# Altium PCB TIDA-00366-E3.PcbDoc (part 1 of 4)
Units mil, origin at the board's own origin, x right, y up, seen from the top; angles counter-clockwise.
Board outline 6298.95 x 6141.73 mil, 4 copper layers (Top Layer, GND, PWR, Bottom Layer), stack 79.834 mil thick; 362 components, 168 nets, 919 pads, 271 vias.
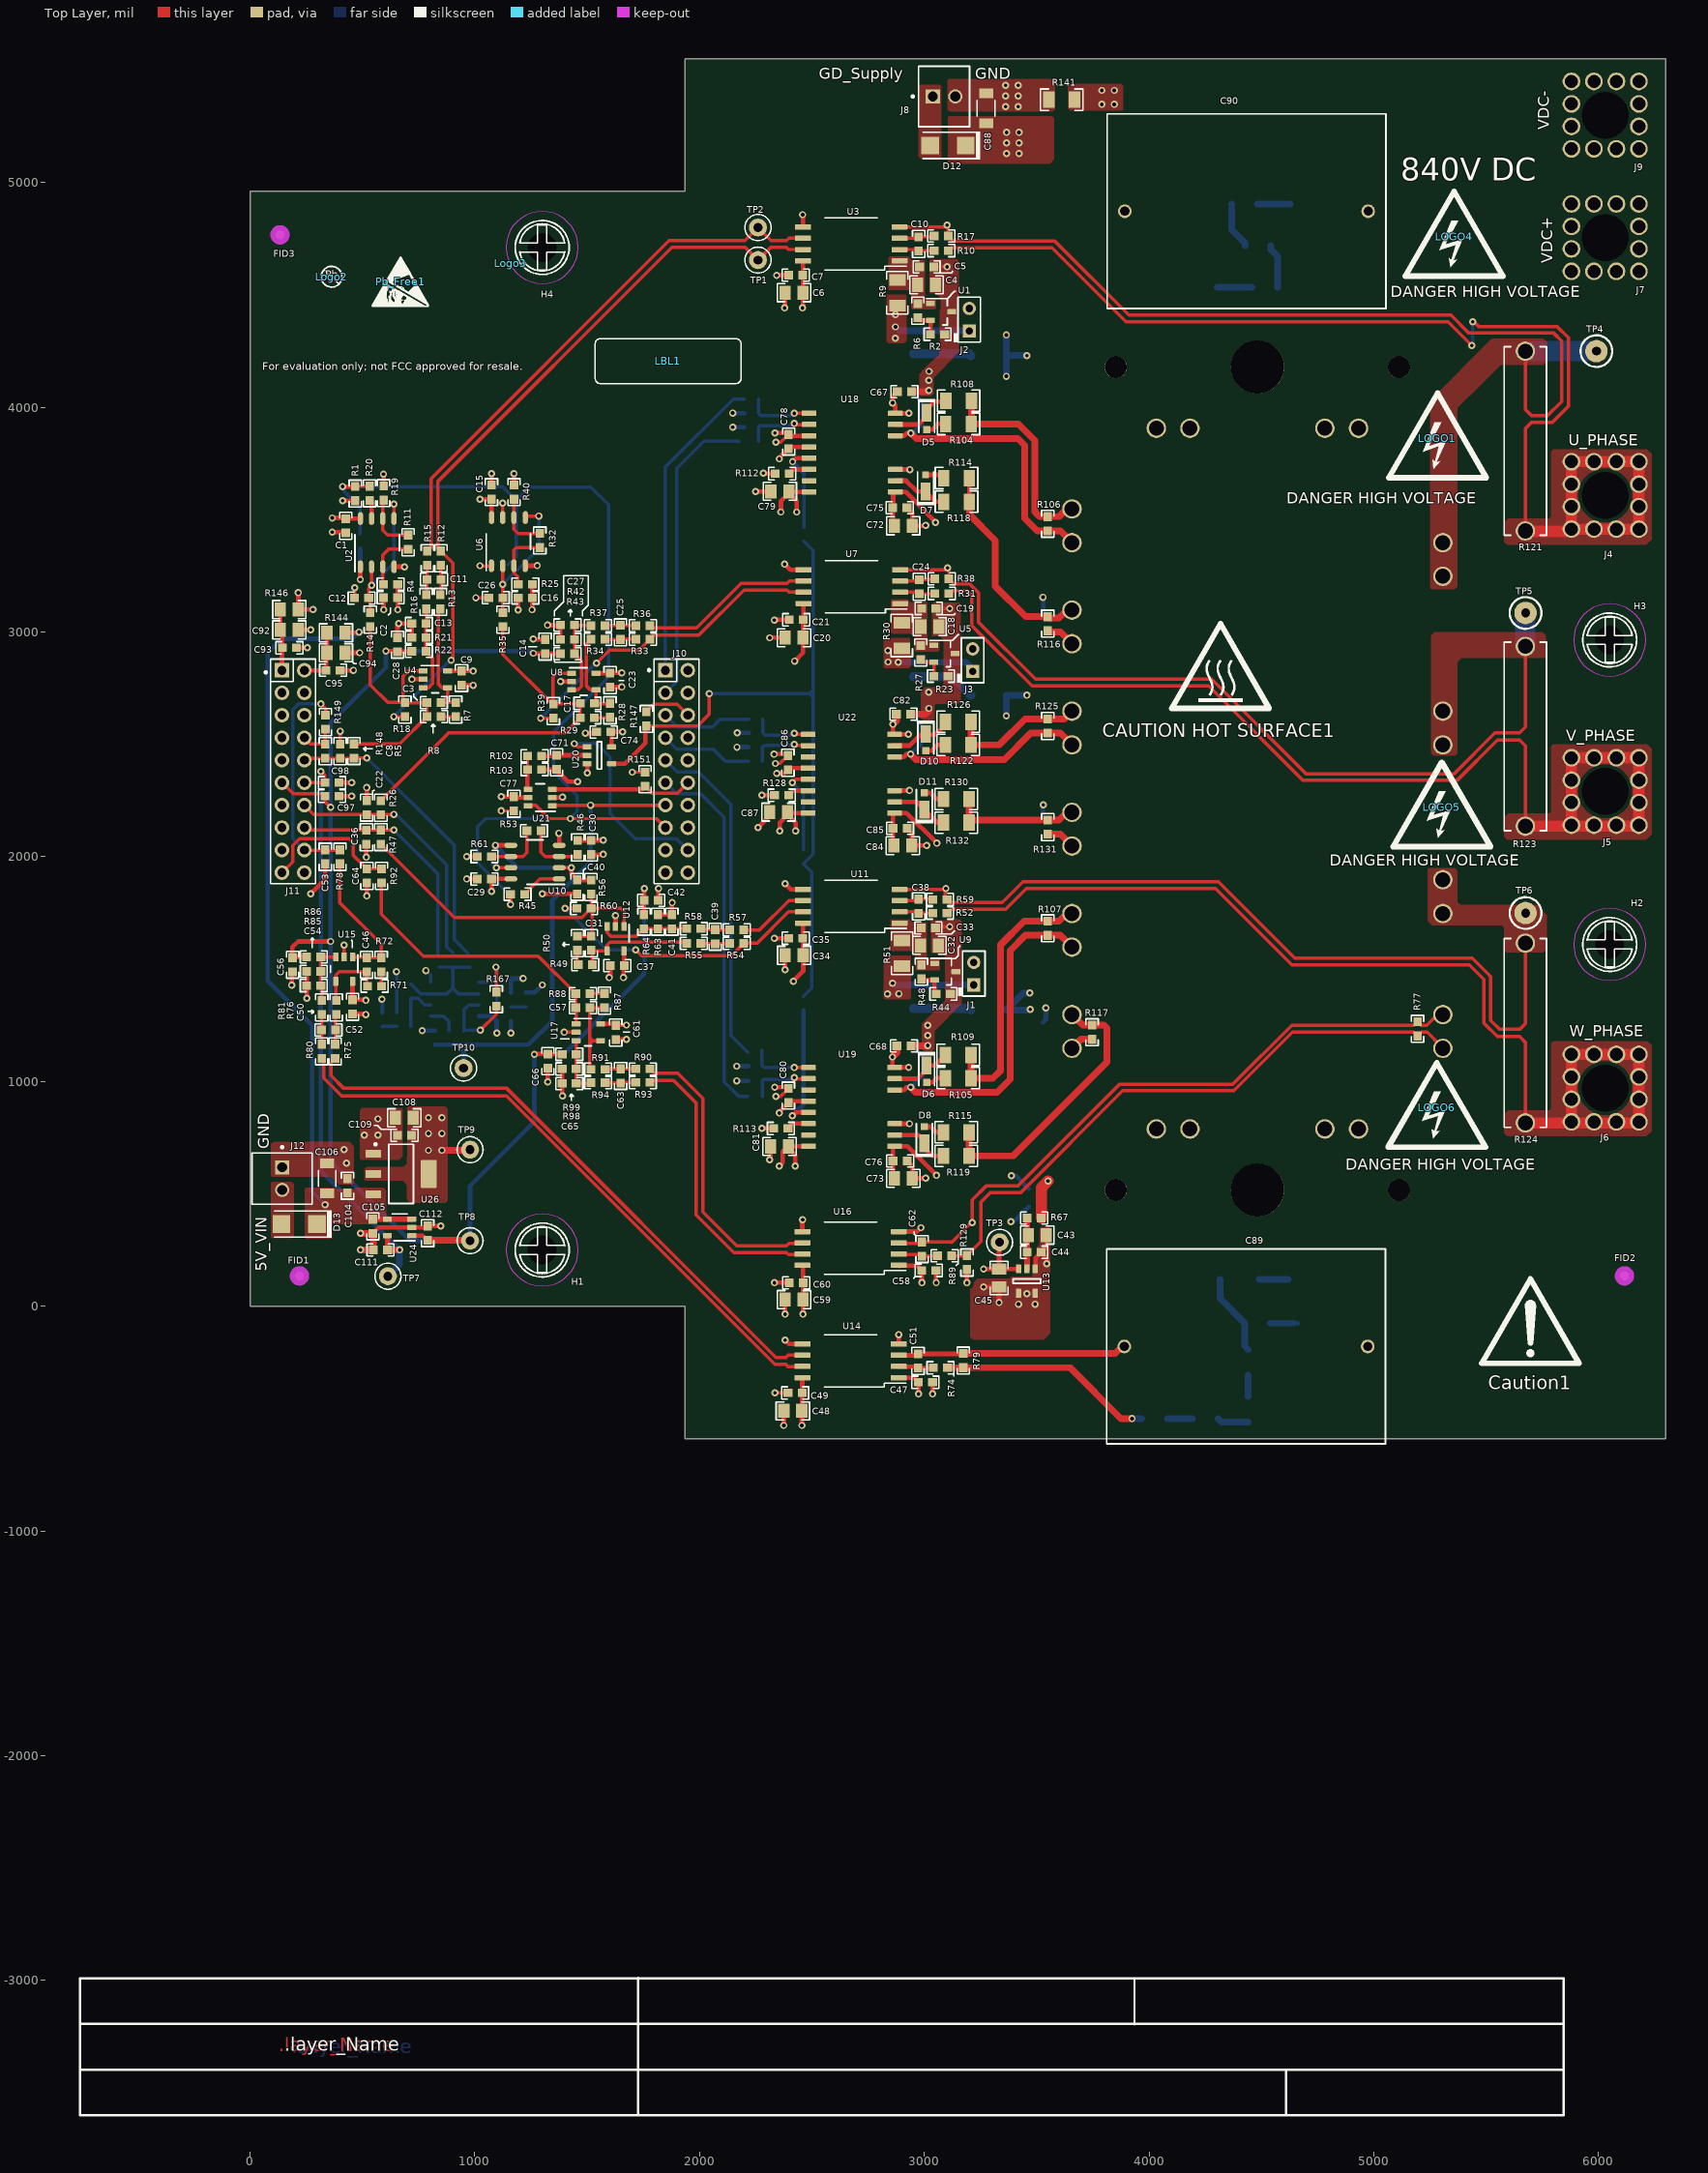
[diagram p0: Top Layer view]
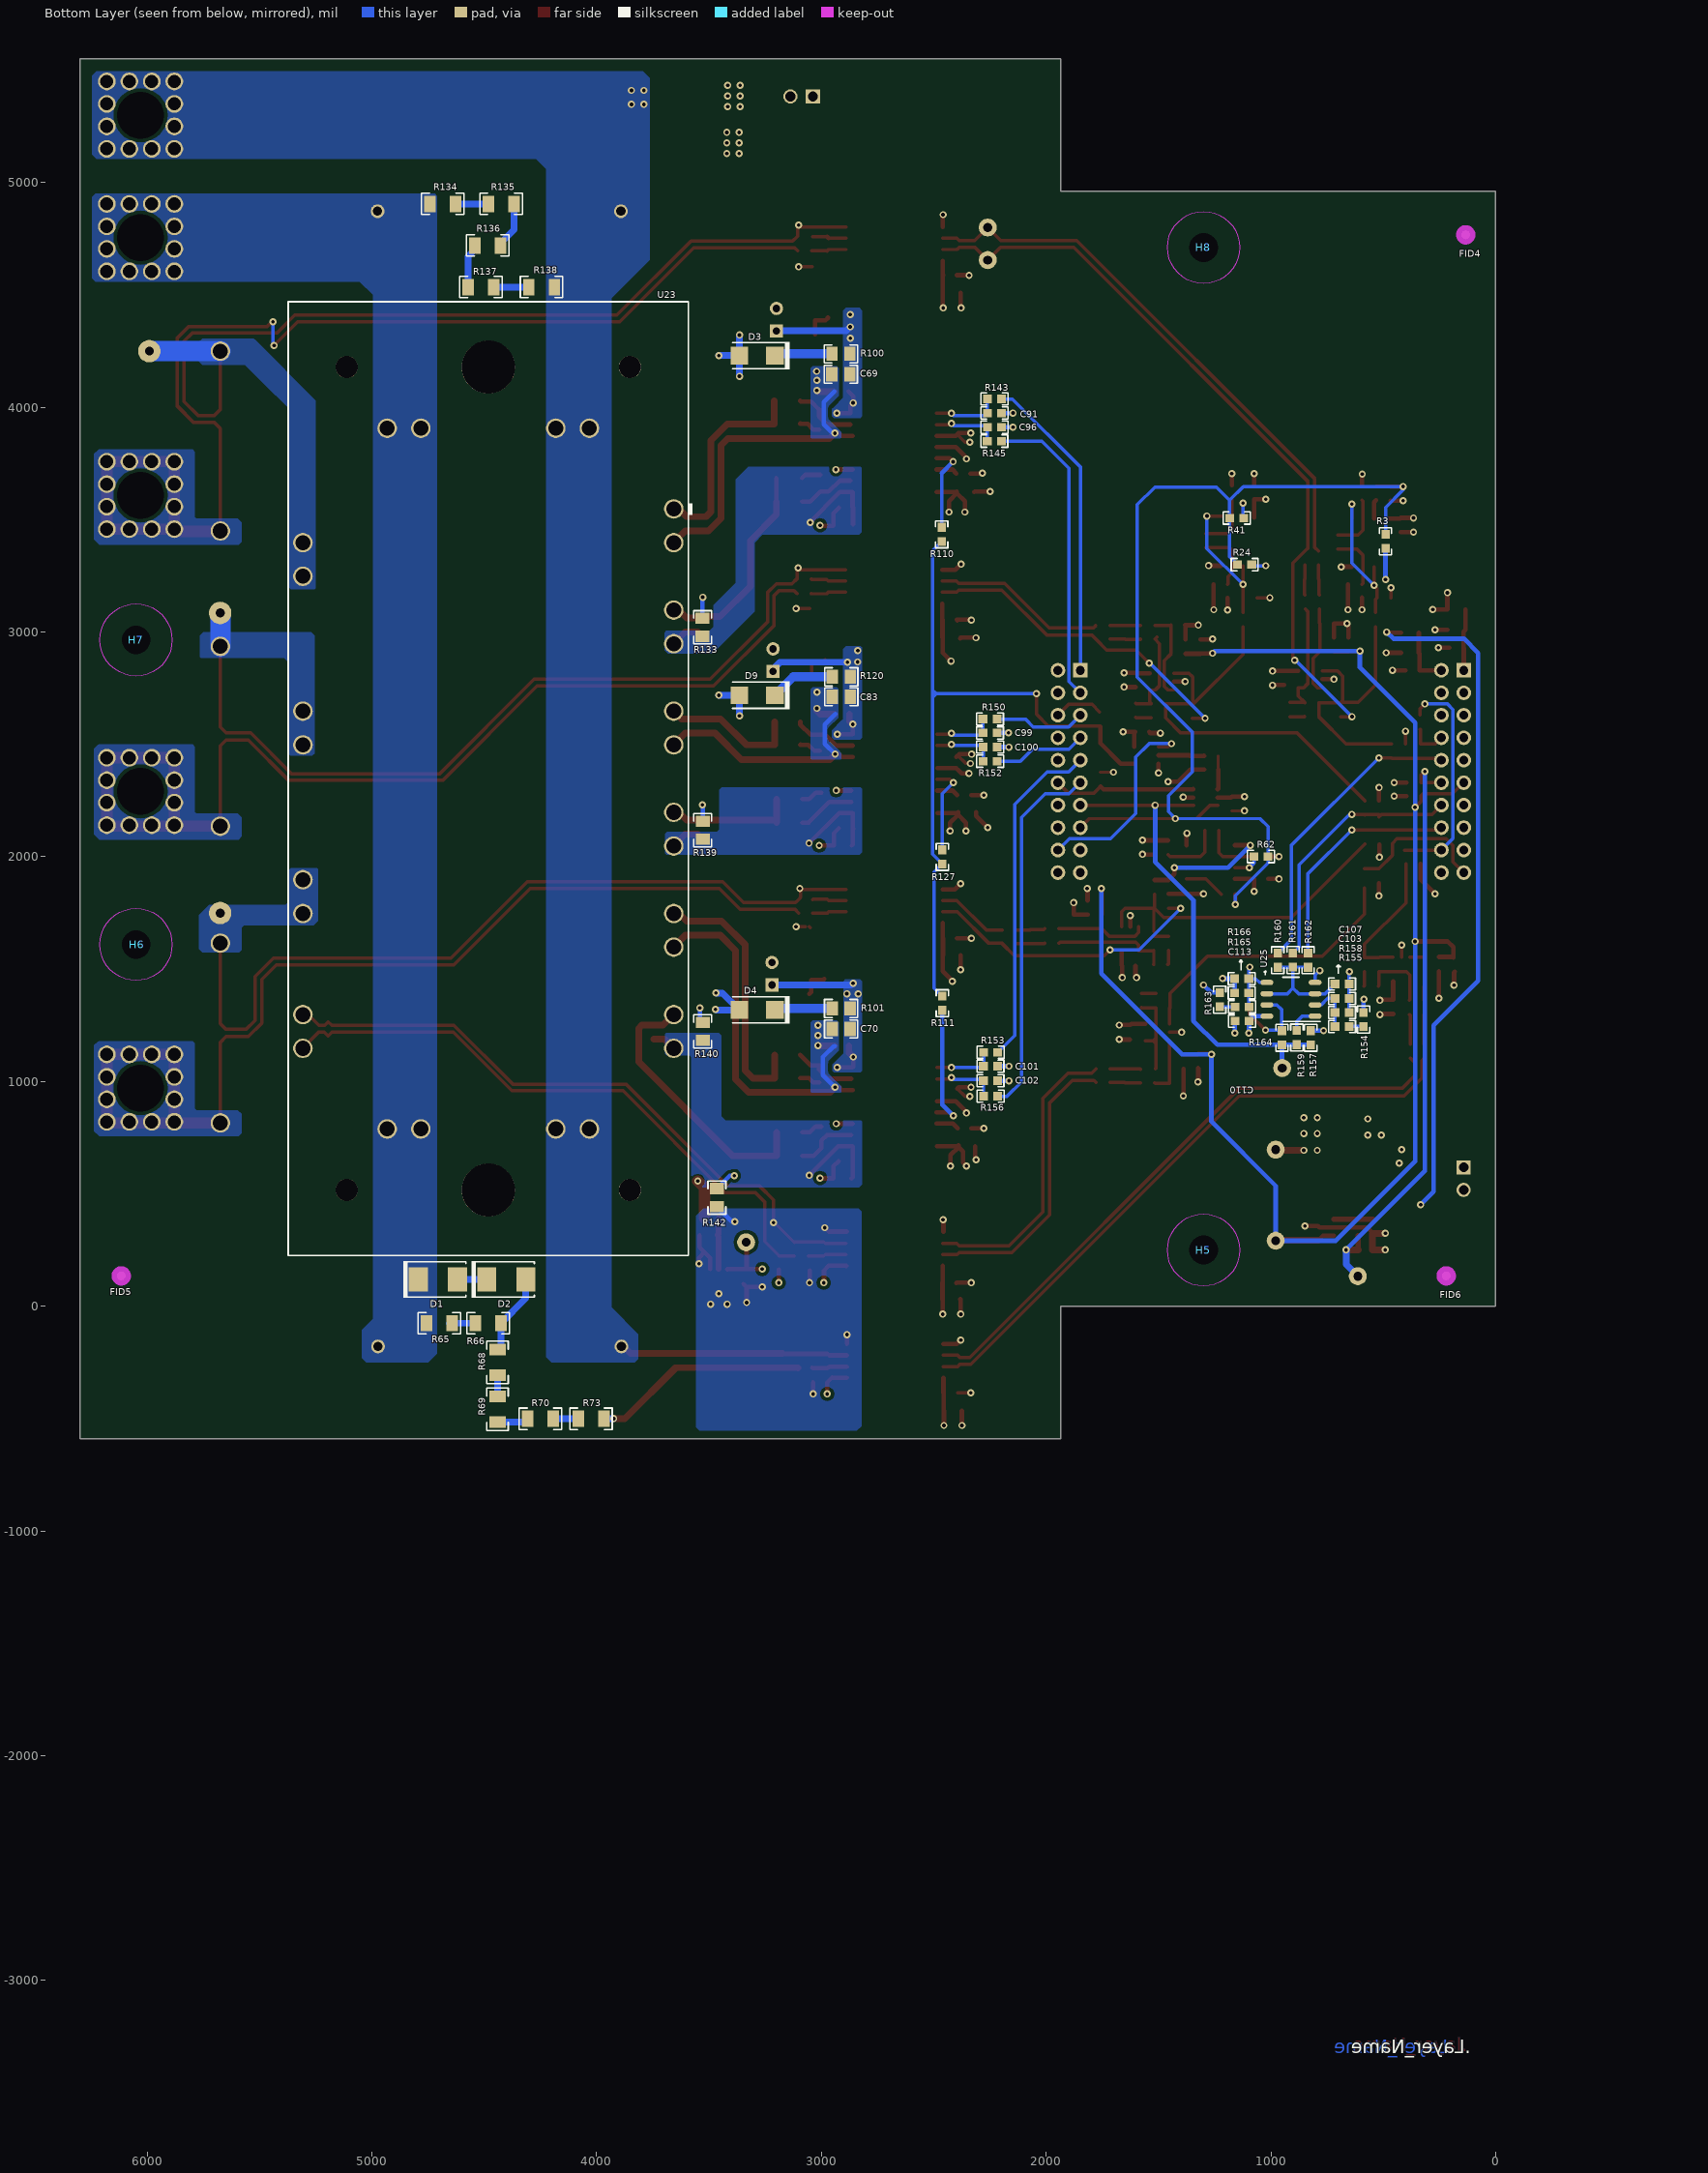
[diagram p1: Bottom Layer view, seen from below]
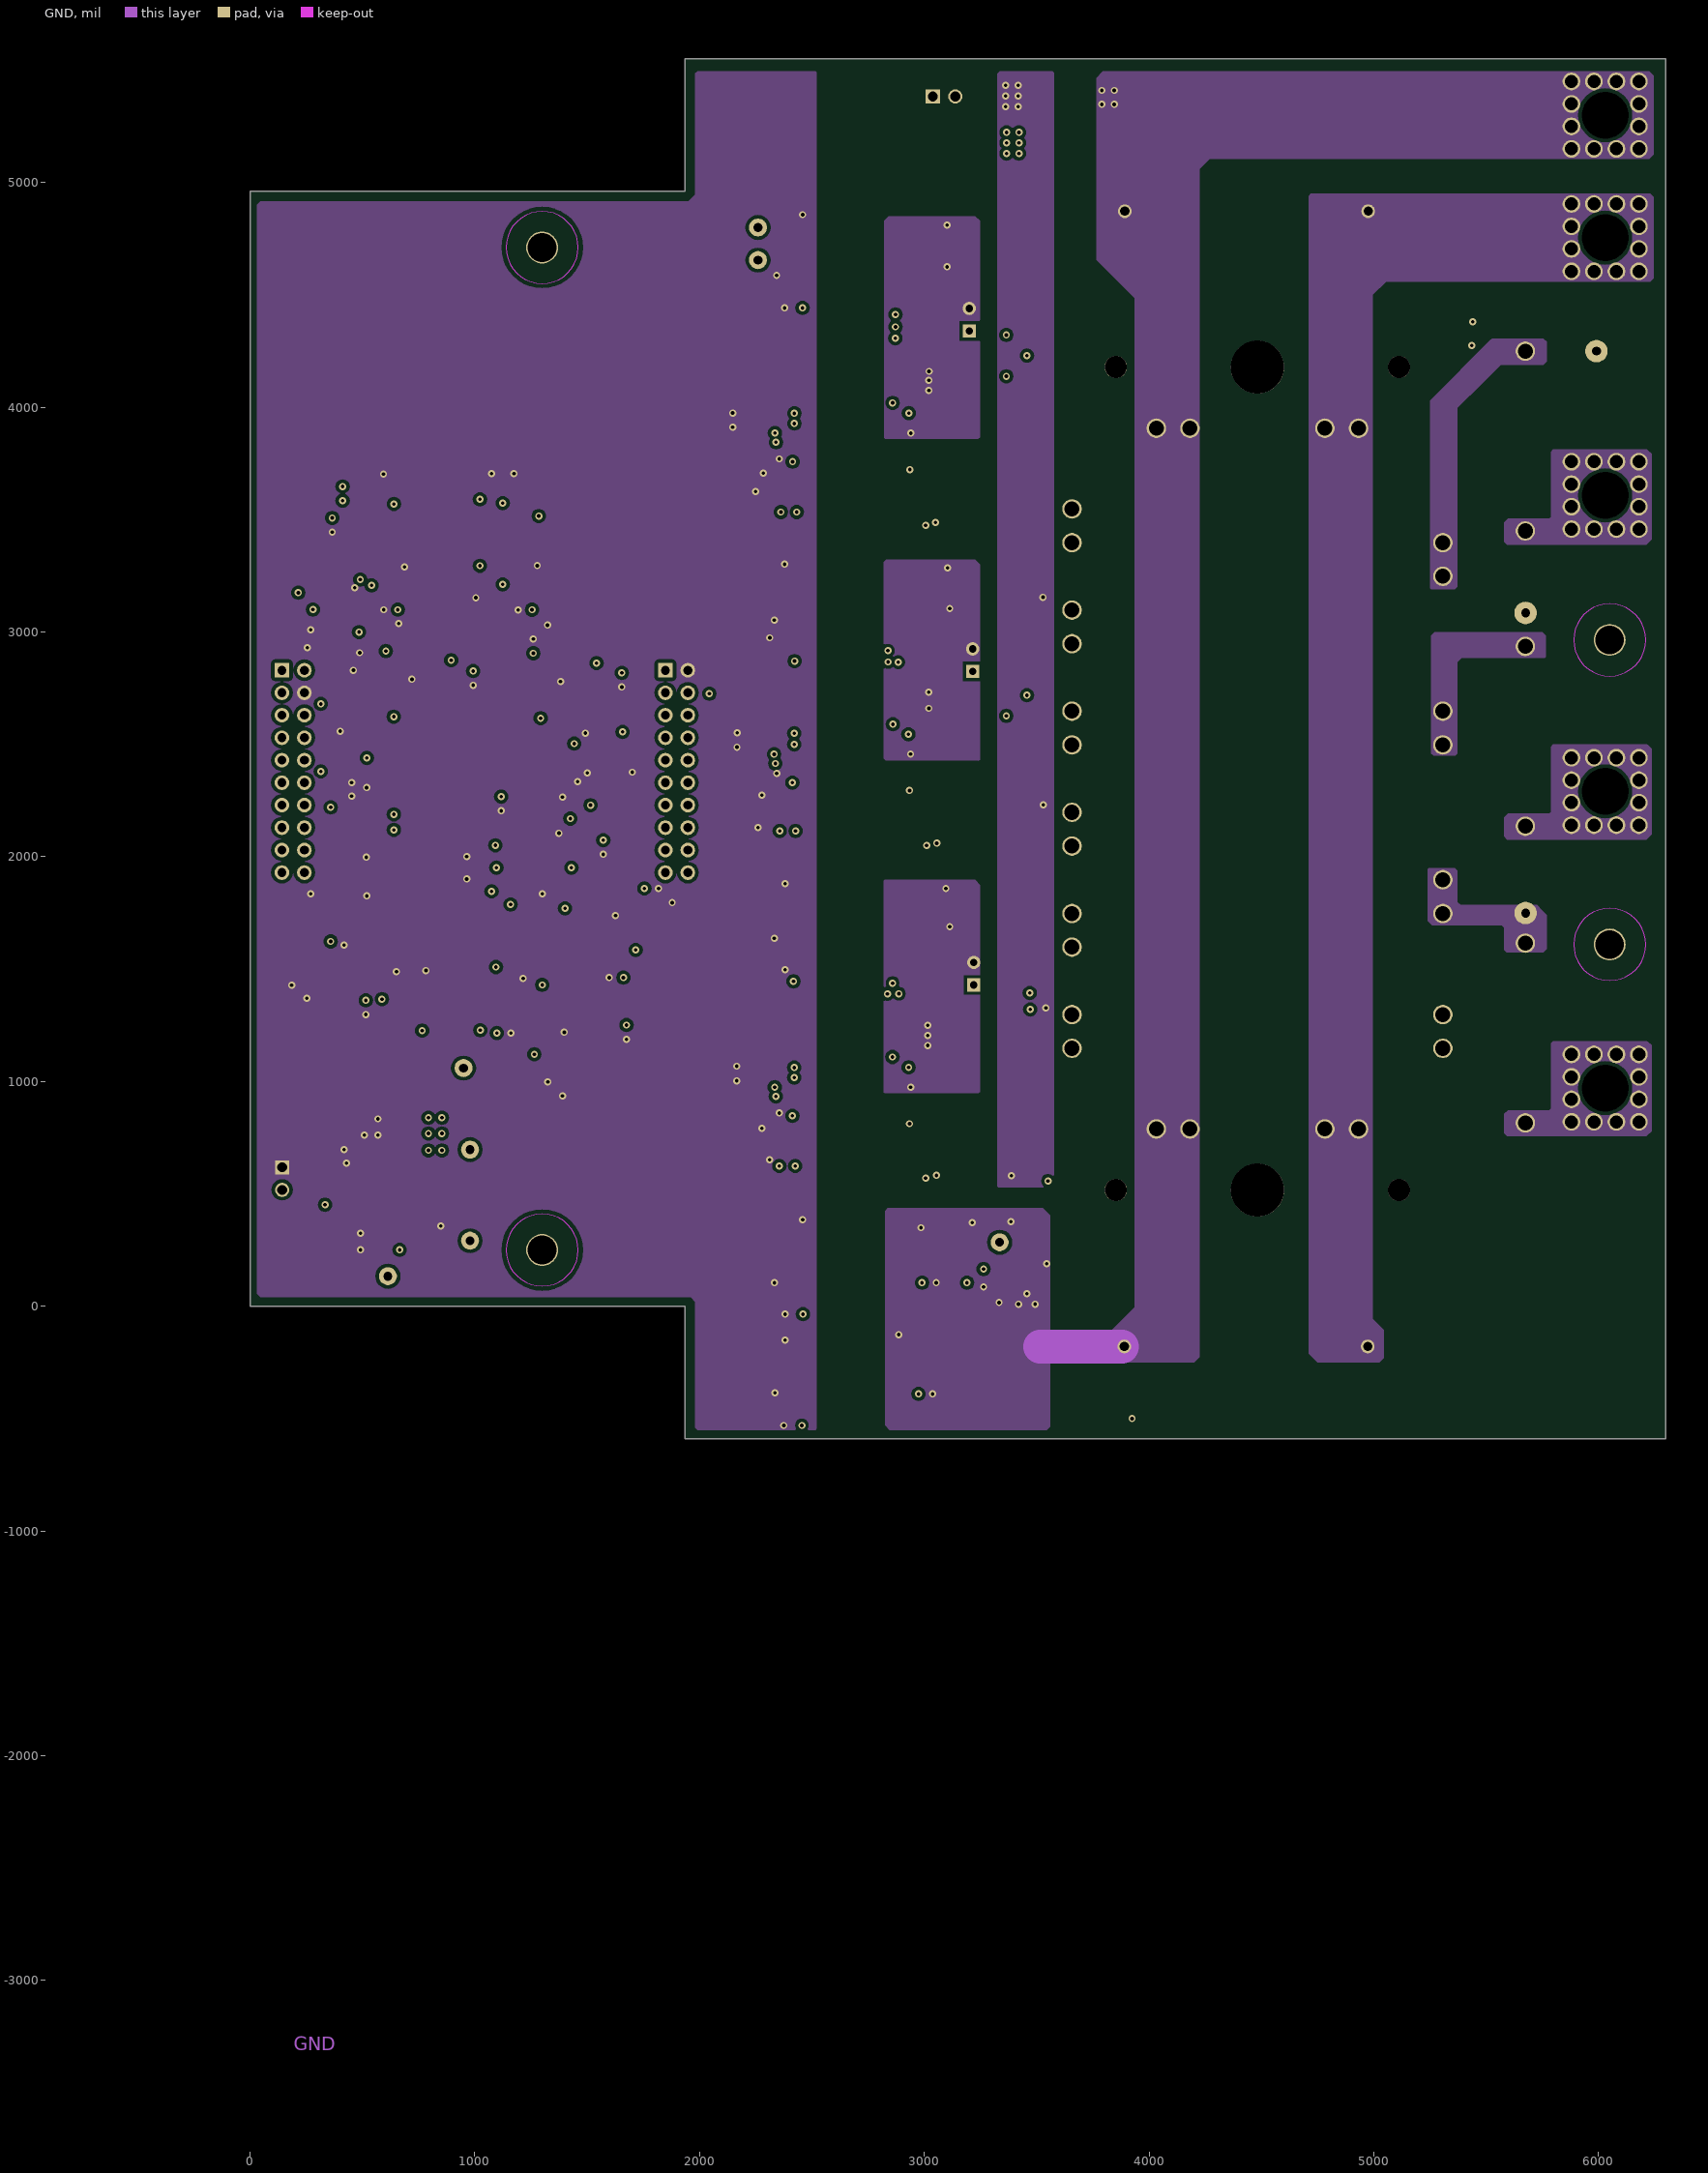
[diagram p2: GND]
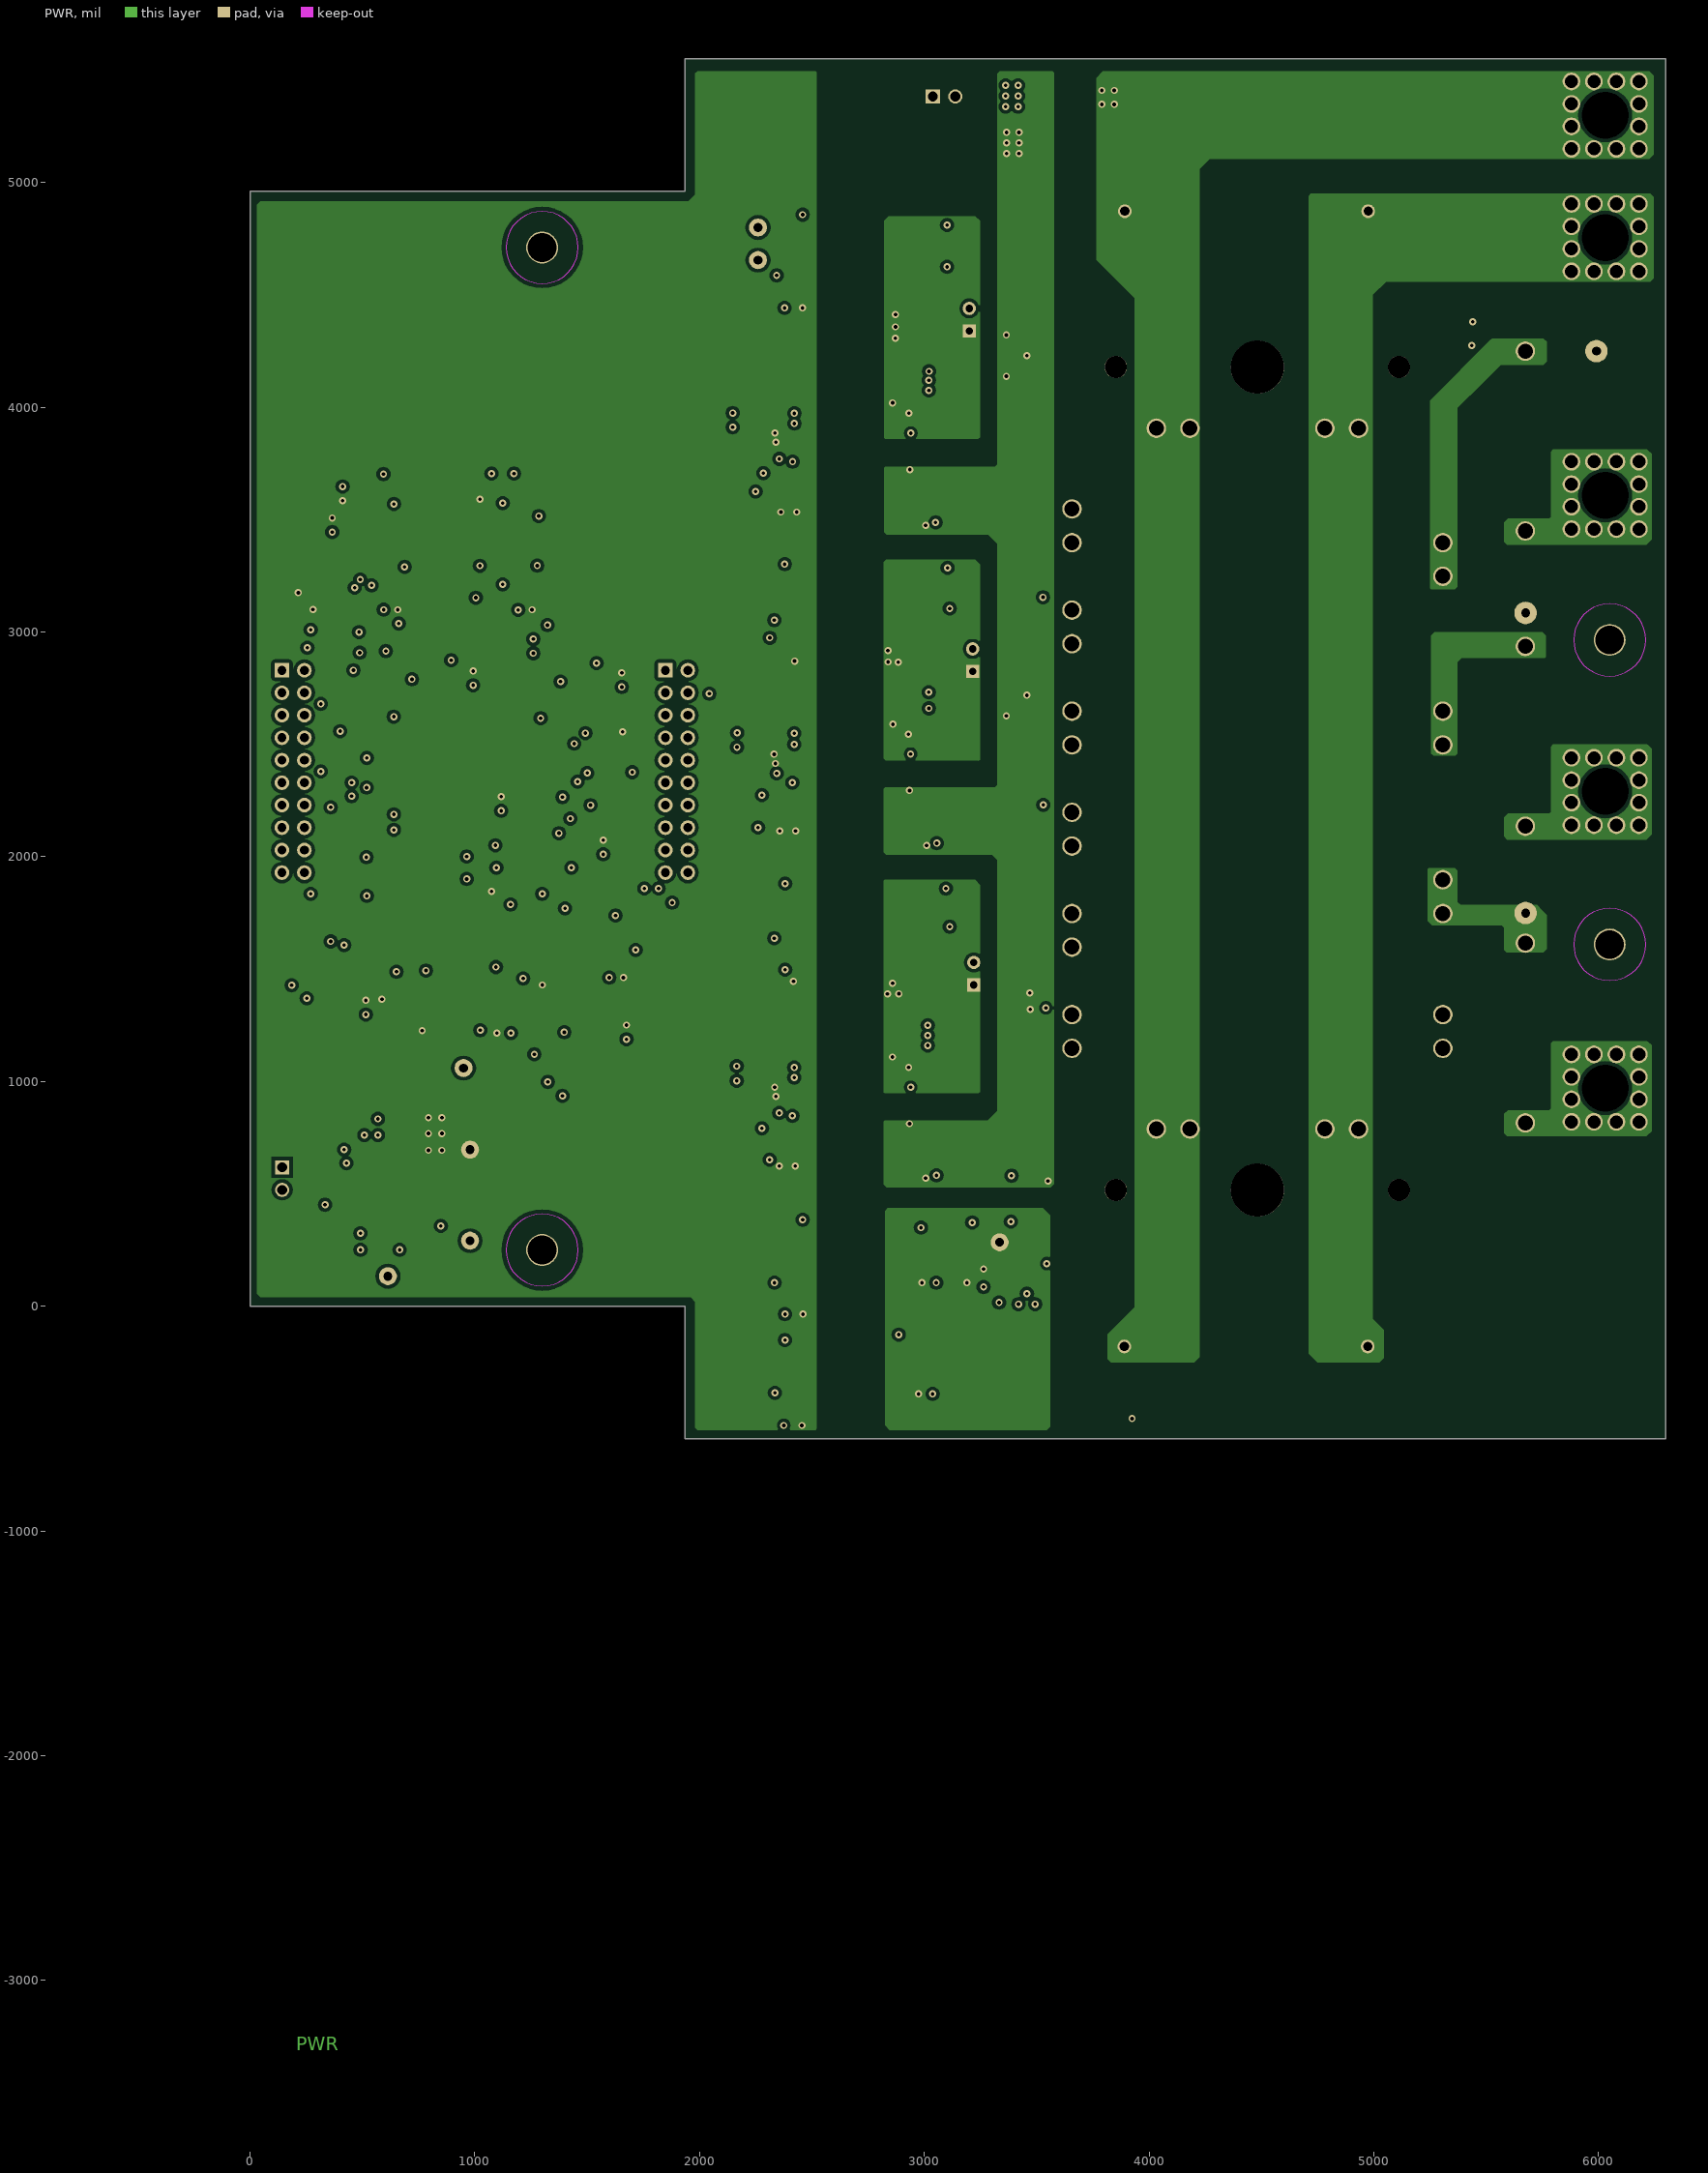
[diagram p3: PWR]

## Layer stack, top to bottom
Top Solder: solder mask 0.4, Solder Resist, Dk 3.5
Top Layer: signal copper 1.4
Dielectric1: core 59.2, FR-4, Dk 4.8
GND: signal copper 1.417
Dielectric 2: prepreg 5, Dk 4.2
PWR: signal copper 1.417
Dielectric 3: core 10, Dk 4.2
Bottom Layer: signal copper 1.4
Bottom Solder: solder mask 0.4, Solder Resist, Dk 3.5

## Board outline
0,0 0,4960.63 1934.73,4960.63 1934.73,5551.18 6298.95,5551.18 6298.95,-590.55 1934.73,-590.55 1934.73,0

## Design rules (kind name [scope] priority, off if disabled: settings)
AcuteAngle [All] p1: minimum=4.50000000000000E+0001 checktracksonly=FALSE
AssemblyTestPointUsage [All] p1: valid=2
Clearance Clearance_Wtop [InNet('W_TOP_REF') vs InNet('W_PHASE')] p1: gap=15 ignorepadtopadclearanceinfootprint=FALSE except(0: Arc-Hole Track-Hole SMDPad-Hole THPad-Hole Via-Hole Fill-Hole Poly-Hole Region-Hole Text-Hole)
Clearance Clearance_Vtop [InNet('V_TOP_REF') vs InNet('V_PHASE')] p2: gap=15 ignorepadtopadclearanceinfootprint=FALSE except(0: Arc-Hole Track-Hole SMDPad-Hole THPad-Hole Via-Hole Fill-Hole Poly-Hole Region-Hole Text-Hole)
Clearance Clearance_utop [InNet('U_TOP_REF') vs InNet('U_PHASE')] p3: gap=15 ignorepadtopadclearanceinfootprint=FALSE except(0: Arc-Hole Track-Hole SMDPad-Hole THPad-Hole Via-Hole Fill-Hole Poly-Hole Region-Hole Text-Hole)
Clearance Clearance_MTG_COPPER [InPadClass('MTG') vs InPolygon] p4: gap=40 ignorepadtopadclearanceinfootprint=FALSE except(0: Arc-Hole Track-Hole SMDPad-Hole THPad-Hole Via-Hole Fill-Hole Poly-Hole Region-Hole Text-Hole)
Clearance Clearance_Boardedge_poly [OnCopper and InPolygon vs IsKeepOut] p5: gap=20 ignorepadtopadclearanceinfootprint=FALSE except(0: Arc-Hole Track-Hole SMDPad-Hole THPad-Hole Via-Hole Fill-Hole Poly-Hole Region-Hole Text-Hole)
Clearance "Shape to Shape" [InPolygon vs InPolygon] p6: gap=20 ignorepadtopadclearanceinfootprint=FALSE except(0: Arc-Hole Track-Hole SMDPad-Hole THPad-Hole Via-Hole Fill-Hole Poly-Hole Region-Hole Text-Hole)
Clearance "shape to all" [InPolygon] p7: gap=15 ignorepadtopadclearanceinfootprint=FALSE except(0: Arc-Hole Track-Hole SMDPad-Hole THPad-Hole Via-Hole Fill-Hole Poly-Hole Region-Hole Text-Hole)
Clearance "Clearance_via_thr pin" [IsVia vs IsThruPin] p8: gap=8 ignorepadtopadclearanceinfootprint=FALSE except(0: Arc-Hole Track-Hole SMDPad-Hole THPad-Hole Via-Hole Fill-Hole Poly-Hole Region-Hole Text-Hole)
Clearance "SMD to Via" [IsSMTPin vs IsVia] p9: gap=8 ignorepadtopadclearanceinfootprint=FALSE except(0: Arc-SMDPad Arc-Hole Track-Hole SMDPad-Hole THPad-Hole Via-Hole Fill-Hole Poly-Hole Region-Hole Text-Hole)
Clearance [All] p10: gap=8 ignorepadtopadclearanceinfootprint=FALSE except(0: Arc-SMDPad Arc-Hole Track-Hole SMDPad-Hole THPad-Hole Via-Hole Fill-Hole Poly-Hole Region-Hole Text-Hole)
DiffPairsRouting DiffPair_DiffPairsRouting [InDifferentialPair ('kan')] p1: maxlimit=10 minlimit=10 mostfreqgap=10 toplayer_minwidth=15 toplayer_maxwidth=15 toplayer_prefwidth=15 midlayer1_minwidth=15 midlayer1_maxwidth=15 midlayer1_prefwidth=15 midlayer2_minwidth=15 midlayer2_maxwidth=15 midlayer2_prefwidth=15 bottomlayer_minwidth=15 bottomlayer_maxwidth=15 bottomlayer_prefwidth=15 maxuncoupledlength=500
DiffPairsRouting DiffPair_DiffPairsRouting_1 [InDifferentialPair ('kan')] p2: maxlimit=10 minlimit=10 mostfreqgap=10 toplayer_minwidth=15 toplayer_maxwidth=15 toplayer_prefwidth=15 midlayer1_minwidth=15 midlayer1_maxwidth=15 midlayer1_prefwidth=15 midlayer2_minwidth=15 midlayer2_maxwidth=15 midlayer2_prefwidth=15 bottomlayer_minwidth=15 bottomlayer_maxwidth=15 bottomlayer_prefwidth=15 maxuncoupledlength=500
DiffPairsRouting [All] p3: maxlimit=100 minlimit=10 mostfreqgap=10 toplayer_minwidth=15 toplayer_maxwidth=15 toplayer_prefwidth=15 midlayer1_minwidth=15 midlayer1_maxwidth=15 midlayer1_prefwidth=15 midlayer2_minwidth=15 midlayer2_maxwidth=15 midlayer2_prefwidth=15 bottomlayer_minwidth=15 bottomlayer_maxwidth=15 bottomlayer_prefwidth=15 maxuncoupledlength=1000
FabricationTestPointUsage TestPointUsage [All] p1: valid=2 allowmultiple=FALSE
FabricationTestpoint Testpoint [All] p1: side=3 testpointundercomponent=TRUE minsize=40 maxsize=100 preferedsize=60 minholesize=0 maxholesize=40 preferedholesize=32 testpointgrid=1 allowsidetop=TRUE allowsidebottom=TRUE usegrid=TRUE gridtolerance=0.01
FanoutControl Fanout_LCC [IsLCC] p1: bgadir=Out bgaviamode=Centered fanoutstyle=Auto fanoutdirection=Alternating viagrid=1 // Fanout_LCC (Default Rule)
FanoutControl Fanout_BGA [IsBGA] p2: bgadir=Out bgaviamode=Centered fanoutstyle=Auto fanoutdirection=Alternating viagrid=1 // Fanout_BGA (Default Rule)
FanoutControl Fanout_Default [All] p4: bgadir=Out bgaviamode=Centered fanoutstyle=Auto fanoutdirection=Alternating viagrid=1 // Fanout_Default (Default Rule)
FanoutControl Fanout_Small [(CompPinCount < 5)] p5: bgadir=Out bgaviamode=Centered fanoutstyle=Auto fanoutdirection=OutThenIn viagrid=1 // Fanout_Small (Default Rule)
HoleSize [All] p1: absolutevalues=TRUE maxlimit=1500 minlimit=7 maxpercent=80.000 minpercent=20.000
MatchedLengths DiffPair_MatchedLengths [InDifferentialPair ('kan')] p1: tolerance=1000 checknetsindiffpair=TRUE checkdiffpairvsdiffpair=FALSE checkxsignals=FALSE checkothers=FALSE
MatchedLengths DiffPair_MatchedLengths_1 [InDifferentialPair ('kan')] p2: tolerance=1000 checknetsindiffpair=TRUE checkdiffpairvsdiffpair=FALSE checkxsignals=FALSE checkothers=FALSE
MinimumAnnularRing [All] p1: minimumring=5
MinimumAnnularRing MinimumAnnularRing_ThermalPadVias [IsVia and InAnyComponent] p2: minimumring=5.91
MinimumSolderMaskSliver MinimumSolderMaskSliver_Logo [InComponentClass('Logo') vs InComponentClass('Logo')] p1: minsoldermaskwidth=0.7
MinimumSolderMaskSliver [All] p2: minsoldermaskwidth=3.94
PlaneClearance [All] p1: clearance=15
PlaneConnect [All] p1: planeconnectstyle=Direct reliefexpansion=10 reliefentries=4 reliefconductorwidth=10 reliefairgap=10
PolygonConnect [All] p1: connectstyle=Direct reliefconductorwidth=10 reliefentries=4 polygonreliefangle="90 Angle" airgapwidth=10
RoutingVias RoutingVias_power [InNetClass('POWER')] p1: holewidth=16 width=32 viastyle="Through Hole" minholewidth=7.87 minwidth=19.68 maxholewidth=16 maxwidth=32
RoutingVias ThermalPadVias [IsVia and InAnyComponent] p2: holewidth=8 width=20 viastyle="Through Hole" minholewidth=7.87 minwidth=19 maxholewidth=12 maxwidth=24
RoutingVias [All] p3: holewidth=12 width=24 viastyle="Through Hole" minholewidth=12 minwidth=24 maxholewidth=16 maxwidth=32
SMDToCorner [All] p1: distance=30000
SilkToSilkClearance [All] p1: silktosilkclearance=5
SilkToSolderMaskClearance SilkscreenOverComponentPads [IsPad] p1: minsilkscreentomaskgap=5 clearancetoexposedcopper=TRUE
SolderMaskExpansion [All] p1: expansion=3
Width Width_power [InNetClass('pwr')] p1: maxlimit=200 minlimit=8 preferedwidth=20
Width [All] p2: maxlimit=250 minlimit=12 preferedwidth=20 checkconnectedcopper=TRUE
16 further rules are at their usual default settings.

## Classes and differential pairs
component class Label: LBL1
component class AssemblyNote: ZZ1 ZZ2 ZZ3 ZZ4
component class Header: J1 J2 J3 J10 J11
pad class MTG: H1-1 H2-1 H3-1 H4-1 H5-0 H6-0 H7-0 H8-0
component class FiducialMark: FID1 FID2 FID3 FID4 FID5 FID6
component class TIDA-00366-E3_EVM_Hardware: Caution1 "CAUTION HOT SURFACE1" FID1 FID2 FID3 FID4 FID5 FID6 H1 H2 H3 H4 H5 H6 H7 H8 LBL1 LOGO1 Logo2 Logo3 LOGO4 LOGO5 LOGO6 Pb_Free1 ZZ1 ZZ2 ZZ3 ZZ4
component class "TIDA-00366-E3_Current sense": C1 C2 C3 C4 C5 C6 C7 C8 C9 C10 C11 C12 C13 C14 C15 C16 C17 C18 C19 C20 C21 C22 C23 C24 C25 C26 C27 C28 C29 C30 C31 C32 C33 C34 C35 C36 C37 C38 C39 C40 C41 C42 R1 R2 R3 R4 R5 R6 R7 R8 R9 R10 R11 R12 R13 R14 R15 R16 R17 R18 R19 R20 R21 R22 R23 R24 R25 R26 R27 R28 R29 R30 R31 R32 R33 R34 R35 R36 R37 R38 R39 R40 R41 R42 R43 R44 R45 R46 R47 R48 R49 R50 R51 R52 R53 R54 R55 R56 R57 R58 R59 R60 R61 R62 R63 R64 TP1 TP2 U1 U2 U3 U4 U5 U6 U7 U8 U9 U10 U11 U12
component class "TIDA-00366-E3_DC BUS and TEMP Sense": C43 C44 C45 C46 C47 C48 C49 C50 C51 C52 C53 C54 C56 C57 C58 C59 C60 C61 C62 C63 C64 C65 C66 D1 D2 R65 R66 R67 R68 R69 R70 R71 R72 R73 R74 R75 R76 R78 R79 R80 R81 R85 R86 R87 R88 R89 R90 R91 R92 R93 R94 R98 R99 TP3 U13 U14 U15 U16 U17
component class "TIDA-00366-E3_Gate driver and Module": C67 C68 C69 C70 C71 C72 C73 C74 C75 C76 C77 C78 C79 C80 C81 C82 C83 C84 C85 C86 C87 C88 C89 C90 D3 D4 D5 D6 D7 D8 D9 D10 D11 D12 J1 J2 J3 J4 J5 J6 J7 J8 J9 R77 R100 R101 R102 R103 R104 R105 R106 R107 R108 R109 R110 R111 R112 R113 R114 R115 R116 R117 R118 R119 R120 R121 R122 R123 R124 R125 R126 R127 R128 R129 R130 R131 R132 R133 R134 R135 R136 R137 R138 R139 R140 R141 R142 TP4 TP5 TP6 U18 U19 U20 U21 U22 U23
component class "TIDA-00366-E3_MCU Interface": C91 C92 C93 C94 C95 C96 C97 C98 C99 C100 C101 C102 C103 C104 C105 C106 C107 C108 C109 C110 C111 C112 C113 D13 J10 J11 J12 R143 R144 R145 R146 R147 R148 R149 R150 R151 R152 R153 R154 R155 R156 R157 R158 R159 R160 R161 R162 R163 R164 R165 R166 R167 TP7 TP8 TP9 TP10 U24 U25 U26

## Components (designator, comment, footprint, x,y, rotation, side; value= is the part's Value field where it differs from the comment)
C1 "C0603X104K4RACTU" 0603 425.51,3472.34 r270 top value=0.1uF
C2 "C0603X104K4RACTU" 0603 625.51,3152.34 r180 top value=0.1uF
C3 "GRM1885C1H181JA01D" 0603 817.73,2685.45 r0 top value=180pF
C4 "C2012X5R1H475K125AB" 0805_HV 3009.73,4544.45 r180 top value=4.7uF
C5 "GCM188R71H104KA57D" 0603 3009.73,4624.45 r180 top value=0.1uF
C6 "C2012X5R1H475K125AB" 0805_HV 2419.73,4509.45 r0 top value=4.7uF
C7 "GCM188R71H104KA57D" 0603 2427.73,4587.45 r0 top value=0.1uF
C8 "06031C152JAT2A" 0603 400.73,2469.45 r90 top value=1500pF
C9 "GCM188R71H104KA57D" 0603 940.83,2795.36 r90 top value=0.1uF
C10 "885012206040" 0603 2974.73,4726.58 r90 top value=0.01uF
C11 "GRM1885C1H181JA01D" 0603 818.61,3233.45 r180 top value=180pF
C12 "885012206040" 0603 496.74,3150.95 r180 top value=0.01uF
C13 "GRM1885C1H181JA01D" 0603 750.73,3037.45 r180 top value=180pF
C14 "GCM188R71H104KA57D" 0603 1313.06,2935.12 r270 top value=0.1uF
C15 "C0603X104K4RACTU" 0603 1074.21,3621.76 r90 top value=0.1uF
C16 "C0603X104K4RACTU" 0603 1224.21,3151.76 r180 top value=0.1uF
C17 "GRM1885C1H181JA01D" 0603 1501,2682 r0 top value=180pF
C18 "C2012X5R1H475K125AB" 0805_HV 3023.73,3023.45 r180 top value=4.7uF
C19 "GCM188R71H104KA57D" 0603 3019.73,3104.45 r180 top value=0.1uF
C20 "C2012X5R1H475K125AB" 0805_HV 2419.73,2974.45 r0 top value=4.7uF
C21 "GCM188R71H104KA57D" 0603 2429.73,3054.45 r0 top value=0.1uF
C22 "06031C152JAT2A" 0603 518.73,2218.45 r90 top value=1500pF
C23 "GCM188R71H104KA57D" 0603 1602,2786 r90 top value=0.1uF
C24 "885012206040" 0603 2977.08,3201.32 r90 top value=0.01uF
C25 "GRM1885C1H181JA01D" 0603 1647.75,2997.99 r90 top value=180pF
C26 "885012206040" 0603 1092.82,3152.19 r180 top value=0.01uF
C27 "GRM1885C1H181JA01D" 0603 1412.54,3030.62 r180 top value=180pF
C28 "GCM188R71H104KA57D" 0603 655.73,2943.45 r270 top value=0.1uF
C29 "C0603X104K4RACTU" 0603 1042.88,1900.91 r180 top value=0.1uF
C30 "C0603X104K4RACTU" 0603 1517.88,2040.91 r270 top value=0.1uF
C31 "GRM1885C1H181JA01D" 0603 1518,1615 r270 top value=180pF
C32 "C2012X5R1H475K125AB" 0805_HV 3022.73,1605.45 r180 top value=4.7uF
C33 "GCM188R71H104KA57D" 0603 3017.73,1683.45 r180 top value=0.1uF
C34 "C2012X5R1H475K125AB" 0805_HV 2420.73,1561.45 r0 top value=4.7uF
C35 "GCM188R71H104KA57D" 0603 2427.73,1637.45 r0 top value=0.1uF
C36 "06031C152JAT2A" 0603 517.73,2086.45 r270 top value=1500pF
C37 "GCM188R71H104KA57D" 0603 1634,1515 r0 top value=0.1uF
C38 "885012206040" 0603 2974.73,1779.45 r90 top value=0.01uF
C39 "GRM1885C1H181JA01D" 0603 2069.73,1644.45 r90 top value=180pF
C40 "885012206040" 0603 1454.96,1865.91 r270 top value=0.01uF
C41 "GRM1885C1H181JA01D" 0603 1876.41,1710.91 r90 top value=180pF
C42 "GCM188R71H104KA57D" 0603 1784.41,1805.91 r180 top value=0.1uF
C43 "C2012X5R1H475K125AB" 0805_HV 3502.33,316.32 r0 top value=4.7uF
C44 "GCM188R71H104KA57D" 0603 3488.33,240.32 r0 top value=0.1uF
C45 "C2012X5R1H475K125AB" 0805_HV 3332.33,125.32 r270 top value=4.7uF
C46 "885012206040" 0603 518.73,1519.4 r90 top value=0.01uF
C47 "GCM188R71H104KA57D" 0603 3004.73,-338.55 r180 top value=0.1uF
C48 "C2012X5R1H475K125AB" 0805_HV 2414.73,-465.55 r0 top value=4.7uF
C49 "GCM188R71H104KA57D" 0603 2424.73,-385.55 r0 top value=0.1uF
C50 "GCM188R71H104KA57D" 0603 456.13,1332 r90 top value=0.1uF
C51 "885012206040" 0603 2971.73,-243.55 r90 top value=0.01uF
C52 "885012206040" 0603 348.73,1229.4 r180 top value=0.01uF
C53 "GCM188R71H104KA57D" 0603 334.73,1999.45 r270 top value=0.1uF
C54 "885012206040" 0603 283.73,1426.4 r180 top value=0.01uF
C56 "GCM188R71H104KA57D" 0603 188.73,1519.4 r90 top value=0.1uF
C57 "885012206040" 0603 1480.53,1327.91 r180 top value=0.01uF
C58 "GCM188R71H104KA57D" 0603 3019.73,159.45 r180 top value=0.1uF
C59 "C2012X5R1H475K125AB" 0805_HV 2419.73,29.45 r0 top value=4.7uF
C60 "GCM188R71H104KA57D" 0603 2429.73,104.45 r0 top value=0.1uF
C61 "GCM188R71H104KA57D" 0603 1627,1217.95 r90 top value=0.1uF
C62 "885012206040" 0603 2989.73,254.45 r90 top value=0.01uF
C63 "885012206040" 0603 1648.28,1024.45 r270 top value=0.01uF
C64 "GCM188R71H104KA57D" 0603 519.73,1914.45 r270 top value=0.1uF
C65 "885012206040" 0603 1419.73,990.91 r180 top value=0.01uF
C66 "GCM188R71H104KA57D" 0603 1324.73,1090.91 r90 top value=0.1uF
C67 "C1608X7R1H474K080AC" 0603 2910.73,4069.45 r180 top value=0.47uF
C68 "C1608X7R1H474K080AC" 0603 2908.86,1157.86 r180 top value=0.47uF
C69 "C2012X5R1H475K125AB" 0805_HV 2913.73,4146.45 r180 bottom value=4.7uF
C70 "C2012X5R1H475K125AB" 0805_HV 2911.86,1233.86 r180 bottom value=4.7uF
C71 "885012206040" 0603 1364,2420 r270 top value=0.01uF
C72 "C2012X5R1H475K125AB" 0805_HV 2905.73,3472.45 r0 top value=4.7uF
C73 "C2012X5R1H475K125AB" 0805_HV 2905.86,568.86 r0 top value=4.7uF
C74 "GCM188R71H104KA57D" 0603 1573,2555 r180 top value=0.1uF
C75 "GCM188R71H104KA57D" 0603 2890.73,3552.45 r0 top value=0.1uF
C76 "GCM188R71H104KA57D" 0603 2891.86,645.86 r0 top value=0.1uF
C77 "GCM188R71H104KA57D" 0603 1173.57,2235.73 r270 top value=0.1uF
C78 "GCM188R71H104KA57D" 0603 2395.99,3847.45 r270 top value=0.1uF
C79 "C2012X5R1H475K125AB" 0805_HV 2356.99,3625.45 r180 top value=4.7uF
C80 "GCM188R71H104KA57D" 0603 2395.12,936.86 r270 top value=0.1uF
C81 "C2012X5R1H475K125AB" 0805_HV 2356,711 r180 top value=4.7uF
C82 "C1608X7R1H474K080AC" 0603 2906.73,2634.45 r180 top value=0.47uF
C83 "C2012X5R1H475K125AB" 0805_HV 2911.73,2711.45 r180 bottom value=4.7uF
C84 "C2012X5R1H475K125AB" 0805_HV 2904.73,2049.45 r0 top value=4.7uF
C85 "GCM188R71H104KA57D" 0603 2891.73,2126.45 r0 top value=0.1uF
C86 "GCM188R71H104KA57D" 0603 2392.73,2418.45 r270 top value=0.1uF
C87 "C2012X5R1H475K125AB" 0805_HV 2351.73,2198.45 r180 top value=4.7uF
C88 "GRT31CR61H106KE01L" 1206_180 3274.73,5329.45 r90 top value=10uF
C89 "B32774D1505K" B32774_3150x2200x3650 4431,-179 r180 top value=5uF
C90 "B32774D1505K" B32774_3150x2200x3650 4433,4872 r180 top value=5uF
C91 "885012006073" 0603 2229.73,3973.99 r180 bottom value=10pF
C92 "C2012X5R1H475K125AB" 0805_HV 174.73,3009.45 r180 top value=4.7uF
C93 "GCM188R71H104KA57D" 0603 174.73,2929.45 r180 top value=0.1uF
C94 "C2012X5R1H475K125AB" 0805_HV 381.73,2907.45 r0 top value=4.7uF
C95 "C1608X7R1H104K" 0603 369.73,2829.45 r0 top value=0.1uF
C96 "885012006073" 0603 2229.73,3910.99 r180 bottom value=10pF
C97 "GCM188R71H104KA57D" 0603 364.73,2269.45 r0 top value=0.1uF
C98 "GCM188R71H104KA57D" 0603 364.73,2329.45 r0 top value=0.1uF
C99 "885012006073" 0603 2249.73,2550.99 r180 bottom value=10pF
C100 "885012006073" 0603 2248.73,2487.65 r180 bottom value=10pF
C101 "885012006073" 0603 2247.73,1067.99 r180 bottom value=10pF
C102 "885012006073" 0603 2247.73,1002.99 r180 bottom value=10pF
C103 "C0603C821K5RACTU" 0603 683.76,1369.45 r180 bottom value=820pF
C104 "GCM188R71H104KA57D" 0603 433.73,536.45 r90 top value=0.1uF
C105 "GCM188R71H104KA57D" 0603 546.38,355.61 r270 top value=0.1uF
C106 "GRT31CR61H106KE01L" 1206_180 342.73,568.45 r90 top value=10uF
C107 "C0603C821K5RACTU" 0603 683.76,1433.45 r180 bottom value=820pF
C108 "CL21A226MAQNNNE" 0805_HV 685.73,838.45 r180 top value=22uF
C109 "GCM188R71H104KA57D" 0603 686.73,760.45 r180 top value=0.1uF
C110 "GCM188R71H104KA57D" 0603 1128.73,1268.99 r0 bottom value=0.1uF
C111 "GCM188R71H104KA57D" 0603 580.38,250.61 r180 top value=0.1uF
C112 "GCM188R71H104KA57D" 0603 790.38,325.61 r90 top value=0.1uF
C113 "C0603C821K5RACTU" 0603 1129.73,1456.99 r0 bottom value=820pF
Caution1 "CAUTION.  READ USER GUIDE BEFORE USE" IEC_Caution_Medium 5696,-72 r0 top
"CAUTION HOT SURFACE1" "CAUTION HOT SURFACE" IEC_HotSurface_Medium 4317,2848 r0 top
D1 "1SMB5956BT3G" SMB 4705.74,119.45 r180 bottom value=200V
D2 "1SMB5956BT3G" SMB 4401.74,119.45 r180 bottom value=200V
D3 "BYG23T-M3/TR" SMA 3285.73,4229.45 r0 bottom value=1300V
D4 "BYG23T-M3/TR" SMA 3285.73,1318.45 r0 bottom value=1300V
D5 "MSS2P3-M3/89A" MicroSMP 3010,3950 r270 top value=30V
D6 "MSS2P3-M3/89A" MicroSMP 3010,1045 r270 top value=30V
D7 "MSS2P3-M3/89A" MicroSMP 3005,3650 r90 top value=30V
D8 "MSS2P3-M3/89A" MicroSMP 3000,750 r90 top value=30V
D9 "BYG23T-M3/TR" SMA 3285.73,2718.45 r0 bottom value=1300V
D10 "MSS2P3-M3/89A" MicroSMP 3006.23,2520.45 r270 top value=30V
D11 "MSS2P3-M3/89A" MicroSMP 3000,2235 r90 top value=30V
D12 "B1100-13-F" SMA 3104.73,5164.45 r180 top value=100V
D13 "B1100-13-F" SMA 218.73,365.45 r180 top value=100V
FID1 "Fiducial" Fiducial10-20 220,135 r270 top
FID2 "Fiducial" Fiducial10-20 6114.73,135 r270 top
FID3 "Fiducial" Fiducial10-20 133.32,4767 r270 top
FID4 "Fiducial" Fiducial10-20 133.32,4767 r270 bottom
FID5 "Fiducial" Fiducial10-20 6114.73,135 r270 bottom
FID6 "Fiducial" Fiducial10-20 220,135 r270 bottom
H1 "MH 3.2mm" MH3.2_H5_W6_KO8_STARHEAD 1299.63,250 r180 top
H2 "MH 3.2mm" MH3.2_H5_W6_KO8_STARHEAD 6048.95,1609.45 r180 top
H3 "MH 3.2mm" MH3.2_H5_W6_KO8_STARHEAD 6048.95,2964.45 r180 top
H4 "MH 3.2mm" MH3.2_H5_W6_KO8_STARHEAD 1299.63,4710.63 r180 top
H5 "1902C" Keystone_1902C 1299.63,250 r0 bottom
H6 "1902C" Keystone_1902C 6043.95,1609.45 r0 bottom
H7 "1902C" Keystone_1902C 6048.95,2964.45 r0 bottom
H8 "1902C" Keystone_1902C 1299.63,4710.63 r0 bottom
J1 "800-10-002-10-001000" Mill-Max_800-10-002-10-001000 3219.73,1479.45 r90 top
J2 "800-10-002-10-001000" Mill-Max_800-10-002-10-001000 3199.73,4389.45 r90 top
J3 "800-10-002-10-001000" Mill-Max_800-10-002-10-001000 3214.73,2874.45 r90 top
J4 "7461086" Wurth_7461086 6028.73,3607.45 r0 top
J5 "7461086" Wurth_7461086 6028.73,2290.45 r0 top
J6 "7461086" Wurth_7461086 6028.73,970.45 r0 top
J7 "7461086" Wurth_7461086 6028.73,4754.45 r180 top
J8 "282834-2" TEC_282834-2 3087.73,5382.45 r0 top
J9 "7461086" Wurth_7461086 6028.73,5299.45 r180 top
J10 "TSW-110-07-G-D" TSW-110-07-G-D 1897.73,2379.45 r270 top locked
J11 "TSW-110-07-G-D" TSW-110-07-G-D 191.73,2379.45 r270 top locked
J12 "282834-2" TEC_282834-2 142.73,567.45 r270 top
LBL1 "Size: 0.65\" x 0.20 \"" Label_650x200 1860,4205 r180 top
LOGO1 "DANGER HIGH VOLTAGE" IEC_HighVoltage_medium 5283,3862 r0 top
Logo2 "Pb-Free Symbol" Pb-Free_Overlay_Small 363.07,4580.5 r0 top
Logo3 "FCC disclaimer" FCC_disclaimer 1157.73,4639.45 r0 top
LOGO4 "DANGER HIGH VOLTAGE" IEC_HighVoltage_medium 5357,4759 r0 top
LOGO5 "DANGER HIGH VOLTAGE" IEC_HighVoltage_medium 5302,2220 r0 top
LOGO6 "DANGER HIGH VOLTAGE" IEC_HighVoltage_medium 5280,883 r0 top
Pb_Free1 "ESD Susceptible" ESD_Overlay_Medium 669,4558 r0 top
R1 "RC0603JR-0710KL" 0603 468.27,3615.55 r270 top value=10k
R2 "RC0603JR-0710KL" 0603 3058.73,4324.45 r0 top value=10k
R3 "RC0603JR-070RL" 0603 490,3403 r90 bottom value=0
R4 "ERA-3AEB101V" 0603 625.51,3212.34 r0 top value=100
R5 "RC0603FR-07100RL" 0603 462.73,2470.45 r270 top value=100
R6 "RC0603JR-0710KL" 0603 2970.73,4429.45 r270 top value=10k
R7 "RC0603JR-070RL" 0603 914.73,2654.45 r270 top value=0
R8 "ERJ-3EKF7501V" 0603 818.73,2623.45 r180 top value=7.50k
R9 "CRCW1206820RJNEA" 1206 2879.73,4509.45 r90 top value=820
R10 "RC0603JR-070RL" 0603 3074.73,4696.58 r180 top value=0
R11 "RG1608P-1072-B-T5" 0603 703.09,3399.42 r270 top value=10.7k
R12 "RC0603FR-074K7L" 0603 848.61,3328.45 r270 top value=4.70k
R13 "RC0603FR-074K7L" 0603 846.61,3133.45 r270 top value=4.70k
R14 "RC0603JR-070RL" 0603 534.73,3054.45 r90 top value=0
R15 "RC0603FR-074K7L" 0603 788.61,3328.45 r270 top value=4.70k
R16 "RC0603FR-074K7L" 0603 783.61,3133.45 r270 top value=4.70k
R17 "RC0603JR-070RL" 0603 3074.73,4761.58 r180 top value=0
R18 "CRCW06030000Z0EA" 0603 688.75,2654.72 r90 top value=0
R19 "ERA-3AEB101V" 0603 594.09,3617.42 r270 top value=100
R20 "RC0603JR-070RL" 0603 532,3617 r90 top value=0
R21 "ERJ-3EKF7501V" 0603 750.73,2975.45 r0 top value=7.50k
R22 "ERJ-3EKF7501V" 0603 750.73,2913.45 r0 top value=7.50k
R23 "RC0603JR-0710KL" 0603 3073.73,2803.45 r0 top value=10k
R24 "RC0603JR-070RL" 0603 1116.73,3299.82 r0 bottom value=0
R25 "ERA-3AEB101V" 0603 1224.21,3211.76 r0 top value=100
R26 "RC0603FR-07100RL" 0603 581.73,2217.45 r270 top value=100
R27 "RC0603JR-0710KL" 0603 2983.73,2908.45 r270 top value=10k
R28 "RC0603JR-070RL" 0603 1601.04,2651.34 r270 top value=0
R29 "ERJ-3EKF7501V" 0603 1500.26,2618.32 r180 top value=7.50k
R30 "CRCW1206820RJNEA" 1206 2899.73,2984.45 r90 top value=820
R31 "RC0603JR-070RL" 0603 3077.08,3171.32 r180 top value=0
R32 "RG1608P-1072-B-T5" 0603 1289.21,3406.76 r270 top value=10.7k
R33 "RC0603FR-074K7L" 0603 1747.75,2967.99 r180 top value=4.70k
R34 "RC0603FR-074K7L" 0603 1547.75,2967.99 r180 top value=4.70k
R35 "RC0603JR-070RL" 0603 1124.73,3054.45 r90 top value=0
R36 "RC0603FR-074K7L" 0603 1747.75,3027.99 r180 top value=4.70k
R37 "RC0603FR-074K7L" 0603 1547.75,3027.99 r180 top value=4.70k
R38 "RC0603JR-070RL" 0603 3077.08,3236.32 r180 top value=0
R39 "CRCW06030000Z0EA" 0603 1349.68,2647.86 r90 top value=0
R40 "ERA-3AEB101V" 0603 1174.21,3621.76 r270 top value=100
R41 "RC0603JR-070RL" 0603 1152,3507 r0 bottom value=0
R42 "ERJ-3EKF7501V" 0603 1412.06,2966.12 r0 top value=7.50k
R43 "ERJ-3EKF7501V" 0603 1412.06,2903.12 r0 top value=7.50k
R44 "RC0603JR-0710KL" 0603 3084.73,1389.45 r0 top value=10k
R45 "RC0603JR-070RL" 0603 1190,1833 r180 top value=0
R46 "ERA-3AEB101V" 0603 1457.88,2040.91 r90 top value=100
R47 "RC0603FR-07100RL" 0603 581.73,2087.45 r90 top value=100
R48 "RC0603JR-0710KL" 0603 2986.73,1487.45 r270 top value=10k
R49 "RC0603JR-070RL" 0603 1490.96,1519.91 r180 top value=0
R50 "ERJ-3EKF7501V" 0603 1455.96,1614.91 r90 top value=7.50k
R51 "CRCW1206820RJNEA" 1206 2900.73,1570.45 r90 top value=820
R52 "RC0603JR-070RL" 0603 3069.73,1749.45 r180 top value=0
R53 "RG1608P-1072-B-T5" 0603 1262.88,2115.91 r0 top value=10.7k
R54 "RC0603FR-074K7L" 0603 2164.73,1614.45 r180 top value=4.70k
R55 "RC0603FR-074K7L" 0603 1974.73,1614.45 r180 top value=4.70k
R56 "RC0603JR-070RL" 0603 1516.96,1864.91 r90 top value=0
R57 "RC0603FR-074K7L" 0603 2164.73,1674.45 r180 top value=4.70k
R58 "RC0603FR-074K7L" 0603 1974.73,1679.45 r180 top value=4.70k
R59 "RC0603JR-070RL" 0603 3069.73,1809.45 r180 top value=0
R60 "CRCW06030000Z0EA" 0603 1485.96,1769.91 r0 top value=0
R61 "ERA-3AEB101V" 0603 1042.88,2000.91 r0 top value=100
R62 "RC0603JR-070RL" 0603 1044,2001 r180 bottom value=0
R63 "ERJ-3EKF7501V" 0603 1814.41,1710.91 r270 top value=7.50k
R64 "ERJ-3EKF7501V" 0603 1752.41,1710.91 r270 top value=7.50k
R65 "RC1206FR-07200KL" 1206 4699.73,-75.55 r0 bottom value=200k
R66 "RC1206FR-07200KL" 1206 4481.73,-75.55 r0 bottom value=200k
R67 "RC0603JR-070RL" 0603 3488.33,392.32 r180 top value=0
R68 "MCR18EZHJ000" 1206 4440.73,-249.54 r90 bottom value=0
R69 "RC1206FR-07200KL" 1206 4440.73,-458.54 r90 bottom value=200k
R70 "RC1206FR-07200KL" 1206 4249.73,-500.55 r0 bottom value=200k
R71 "RC0603JR-070RL" 0603 553.73,1424.4 r0 top value=0
R72 "RC0603FR-0715KL" 0603 583.73,1519.4 r90 top value=15.0k
R73 "RC1206FR-07200KL" 1206 4024.73,-500.55 r0 bottom value=200k
R74 "CRCW060339R0JNEA" 0603 3071.73,-273.55 r180 top value=39
R75 "RC0603FR-074K7L" 0603 378.73,1134.4 r90 top value=4.70k
R76 "RC0603FR-074K7L" 0603 383.73,1329.4 r90 top value=4.70k
R77 "CRCW06030000Z0EA" 0603 5194,1234 r270 top value=0
R78 "RC0603FR-07100RL" 0603 399.73,1999.45 r90 top value=100
R79 "RC0603FR-072K49L" 0603 3173,-242 r270 top value=2.49k
R80 "RC0603FR-074K7L" 0603 318.73,1134.4 r90 top value=4.70k
R81 "RC0603FR-074K7L" 0603 318.73,1329.4 r90 top value=4.70k
R85 "RC0603FR-0715KL" 0603 283.73,1489.4 r0 top value=15.0k
R86 "ERJ-3EKF7501V" 0603 283.73,1554.4 r0 top value=7.50k
R87 "RC0603JR-070RL" 0603 1576.53,1359.91 r90 top value=0
R88 "RC0603FR-0715KL" 0603 1480.53,1390.91 r180 top value=15.0k
R89 "CRCW060339R0JNEA" 0603 3089.73,224.45 r180 top value=39
R90 "RC0603FR-074K7L" 0603 1746.78,1055.45 r180 top value=4.70k
R91 "RC0603FR-074K7L" 0603 1548.28,1054.45 r180 top value=4.70k
R92 "RC0603FR-07100RL" 0603 584.73,1914.45 r90 top value=100
R93 "RC0603FR-074K7L" 0603 1746.78,995.45 r180 top value=4.70k
R94 "RC0603FR-074K7L" 0603 1548.28,994.45 r180 top value=4.70k
R98 "RC0603FR-0715KL" 0603 1419.73,1055.91 r0 top value=15.0k
R99 "ERJ-3EKF7501V" 0603 1419.73,1120.91 r0 top value=7.50k
R100 "RC0805FR-071R33L" 0805_HV 2912.73,4237.45 r0 bottom value=1.33
R101 "RC0805FR-071R33L" 0805_HV 2911.86,1324.86 r0 bottom value=1.33
R102 "RC0603JR-070RL" 0603 1265.73,2448.23 r0 top value=0
R103 "RC0603JR-0710KL" 0603 1265.73,2388.23 r180 top value=10k
R104 "ERJ-8GEY0R00V" 1206 3151.73,3925.45 r0 top value=0
R105 "ERJ-8GEY0R00V" 1206 3150.86,1014.86 r0 top value=0
R106 "RC0603JR-0710KL" 0603 3548.73,3481.45 r90 top value=10k
R107 "RC0603JR-0710KL" 0603 3548.73,1681.45 r90 top value=10k
R108 "CRCW120616R5FKEA" 1206 3151.99,4028.45 r0 top value=16.5
R109 "CRCW120616R5FKEA" 1206 3151.12,1117.86 r0 top value=16.5
R110 "RC0603JR-070RL" 0603 2464.73,3434 r90 bottom value=0
R111 "RC0603JR-070RL" 0603 2462,1348 r270 bottom value=0
R112 "RC0603FR-0720KL" 0603 2367.73,3704.45 r0 top value=20.0k
R113 "RC0603FR-0720KL" 0603 2361.86,790.86 r0 top value=20.0k
R114 "ERJ-8GEY0R00V" 1206 3142.99,3684.45 r0 top value=0
R115 "ERJ-8GEY0R00V" 1206 3142.12,773.86 r0 top value=0
R116 "RC0603JR-0710KL" 0603 3548.73,3036.45 r90 top value=10k
R117 "RC0603JR-0710KL" 0603 3746,1219 r90 top value=10k
R118 "CRCW120616R5FKEA" 1206 3142.99,3579.45 r0 top value=16.5
R119 "CRCW120616R5FKEA" 1206 3142.12,668.86 r0 top value=16.5
R120 "RC0805FR-071R33L" 0805_HV 2911.73,2800.45 r0 bottom value=1.33
R121 "PWR4412-2SDR0050F" PWR44412-2SD 5673.73,3849.45 r90 top value=0.005
R122 "ERJ-8GEY0R00V" 1206 3150.73,2497.45 r0 top value=0
R123 "PWR4412-2SDR0050F" PWR44412-2SD 5673.73,2535.45 r270 top value=0.005
R124 "PWR4412-2SDR0050F" PWR44412-2SD 5673.73,1215.45 r270 top value=0.005
R125 "RC0603JR-0710KL" 0603 3548.73,2581.45 r90 top value=10k
R126 "CRCW120616R5FKEA" 1206 3150.99,2600.45 r0 top value=16.5
R127 "RC0603JR-070RL" 0603 2462,1999 r90 bottom value=0
R128 "RC0603FR-0720KL" 0603 2364.73,2273.45 r0 top value=20.0k
R129 "ERJ-3EKF2202V" 0603 3189.73,194.45 r90 top value=22.0k
R130 "ERJ-8GEY0R00V" 1206 3141.99,2256.45 r0 top value=0
R131 "RC0603JR-0710KL" 0603 3548.73,2131.45 r90 top value=10k
R132 "CRCW120616R5FKEA" 1206 3141.99,2151.45 r0 top value=16.5
R133 "CRCW08050000Z0EA" 0805_HV 3528.73,3020.45 r90 bottom value=0
R134 "CRCW1206100KJNEA" 1206 4684.73,4904.45 r180 bottom value=100k
R135 "CRCW1206100KJNEA" 1206 4424.73,4904.45 r180 bottom value=100k
R136 "CRCW1206100KJNEA" 1206 4484.73,4719.45 r0 bottom value=100k
R137 "CRCW1206100KJNEA" 1206 4514.73,4534.45 r180 bottom value=100k
R138 "CRCW1206100KJNEA" 1206 4244.73,4534.45 r180 bottom value=100k
R139 "CRCW08050000Z0EA" 0805_HV 3527.73,2117.45 r90 bottom value=0
R140 "CRCW08050000Z0EA" 0805_HV 3527.73,1222.45 r90 bottom value=0
R141 "ERJ-8GEY0R00V" 1206 3610.73,5368.45 r0 top value=0
R142 "CRCW08050000Z0EA" 0805_HV 3464.73,483.45 r90 bottom value=0
R143 "RC0603FR-07100RL" 0603 2229.73,4036.45 r180 bottom value=100
R144 "CRCW08050000Z0EA" 0805_HV 381.73,2996.45 r0 top value=0
R145 "RC0603FR-07100RL" 0603 2230.73,3848.99 r180 bottom value=100
R146 "CRCW08050000Z0EA" 0805_HV 174.73,3099.45 r180 top value=0
R147 "RC0603JR-071KL" 0603 1763,2613 r90 top value=1.0k
R148 "CRCW06030000Z0EA" 0603 334.73,2469.45 r270 top value=0
R149 "CRCW06030000Z0EA" 0603 335.73,2598.45 r90 top value=0
R150 "RC0603FR-07100RL" 0603 2249.73,2612.45 r180 bottom value=100
R151 "RC0603JR-0710KL" 0603 1757.73,2344.45 r270 top value=10k
R152 "RC0603FR-07100RL" 0603 2248.73,2424.45 r180 bottom value=100
R153 "RC0603FR-07100RL" 0603 2246.73,1129.45 r180 bottom value=100
R154 "RG1608P-201-B-T5" 0603 587.76,1275.45 r270 bottom value=200
R155 "RG1608P-123-B-T5" 0603 683.76,1244.45 r0 bottom value=12.0k
R156 "RC0603FR-07100RL" 0603 2246.73,934.45 r180 bottom value=100
R157 "RC0603JR-0710KL" 0603 822.76,1194.45 r90 bottom value=10k
R158 "PHT0603Y1002BGT200" 0603 683.76,1306.45 r180 bottom value=10.0k
R159 "RC0603JR-070RL" 0603 885,1195 r270 bottom value=0
R160 "PHT0603Y1002BGT200" 0603 969.73,1539.45 r270 bottom value=10.0k
R161 "PHT0603Y1002BGT200" 0603 901.76,1540.45 r270 bottom value=10.0k
R162 "PHT0603Y1002BGT200" 0603 834.73,1539.45 r270 bottom value=10.0k
R163 "ERJ-3GEY0R00V" 0603 1227.73,1363.99 r270 bottom value=0
R164 "RC0603JR-070RL" 0603 950.73,1194.45 r270 bottom value=0
R165 "RG1608P-822-B-T5" 0603 1128.73,1331.99 r180 bottom value=8.20k
R166 "PHT0603Y1002BGT200" 0603 1129.73,1393.99 r0 bottom value=10.0k
R167 "CRCW06035M11FKEA" 0603 1095.73,1366.73 r270 top value=5.11Meg
TP1 "5000" Keystone5000 2259.73,4654.45 r0 top
TP2 "5000" Keystone5000 2259.73,4799.45 r0 top
TP3 "5000" Keystone5000 3334.73,284.45 r0 top
TP4 "TESTPOINT" PAD_100mil-40milhole 5989.73,4249.45 r0 top
TP5 "TESTPOINT" PAD_100mil-40milhole 5674.73,3084.45 r0 top
TP6 "TESTPOINT" PAD_100mil-40milhole 5674.73,1749.45 r90 top
TP7 "5000" Keystone5000 613.38,133.61 r90 top
TP8 "5000" Keystone5000 978.73,291.45 r90 top
TP9 "5000" Keystone5000 978.73,696.45 r90 top
TP10 "5000" Keystone5000 949.73,1059.45 r90 top
U1 "TL431BQDBZT" DBZ0003A_N 3074.73,4424.45 r0 top
U2 "TLC372QDR" D0008A_N 565.51,3397.34 r90 top
U3 "AMC1301DWVR" DWV0008A 2674.73,4726.58 r180 top
U4 "OPA320AIDBVR" DBV0005A_N 824.73,2789.45 r0 top
U5 "TL431BQDBZT" DBZ0003A_N 3088.73,2903.45 r0 top
U6 "TLC372QDR" D0008A_N 1149.21,3401.76 r90 top
U7 "AMC1301DWVR" DWV0008A 2677.08,3201.32 r180 top
U8 "OPA320AIDBVR" DBV0005A_N 1485.06,2779.12 r0 top
U9 "TL431BQDBZT" DBZ0003A_N 3092.73,1488.45 r0 top
U10 "TLC372QDR" D0008A_N 1267.88,1975.91 r180 top
U11 "AMC1301DWVR" DWV0008A 2674.73,1779.45 r180 top
U12 "OPA320AIDBVR" DBV0005A_N 1625.96,1634.91 r270 top
U13 "TLV70450DBVR" DBV0005A_N 3456,112 r270 top
U14 "AMC1311DWVR" DWV0008A 2671.57,-243 r180 top
U15 "OPA320AIDBVR" DBV0005A_N 418.73,1499.4 r270 top
U16 "AMC1311DWVR" DWV0008A 2671.57,257 r180 top
U17 "OPA320AIDBVR" DBV0005A_N 1504.73,1218.91 r0 top
U18 "UCC21530DWK" DWK0014A 2679,3798 r0 top
U19 "UCC21530DWK" DWK0014A 2675.93,887 r0 top
U20 "SN74LVC1G32DBVR" DBV0005A_N 1554,2451 r0 top
U21 "SN74LVC1G11DBVR" DBV0006A_N 1291,2263 r180 top
U22 "UCC21530DWK" DWK0014A 2674.93,2369 r0 top
U23 "MIXA60W1200TED" IXYS_E2 4481.73,2347.45 r270 bottom locked
U24 "REF2033AIDDCR" DDC0005A_N 665.38,350.61 r180 top
U25 "TLC372QDR" D0008A_N 910.76,1365.45 r0 bottom
U26 "TLV1117-33IDCY" DCY0003A_N 671.73,588.45 r0 top
ZZ1 "This Assembly Note is for PCB labels only" AssemblyNoteLabel 64.73,6629.45 r0 top
ZZ2 "These assemblies are ESD sensitive, ESD precautions shall be observed." AssemblyNote 1419.73,9185.45 r0 top
ZZ3 "These assemblies must be clean and free from flux and all contaminants. Use of no clean flux is not acceptable." AssemblyNote 1419.73,9100.45 r0 top
ZZ4 "These assemblies must comply with workmanship standards IPC-A-610 Class 2, unless otherwise specified." AssemblyNote 1419.73,9025.45 r0 top

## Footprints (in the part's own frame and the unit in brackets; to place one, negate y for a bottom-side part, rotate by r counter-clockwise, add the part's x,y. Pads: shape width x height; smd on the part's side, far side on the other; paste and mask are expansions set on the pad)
0603 [mm] "0603 from SM-752 data"
  rect 1x0.95 smd: 1(-0.8,0) 2(0.8,0)
  silkscreen extent -1.52,-0.69 1.52,0.69, body extent -0.87,-0.47 0.87,0.47, height 1
0805_HV [mil] "0805 with 30mil clearance between pads"
  rect 50x63 smd: 1(-40,0) 2(40,0)
  silkscreen extent -74,-40 74,40, body extent -43,-29 43,29, height 57
1206 [mm] "1206 from SM-752 data"
  rect 1.3x1.85 smd: 1(-1.45,0) 2(1.45,0)
  silkscreen extent -2.4,-1.21 2.4,1.21, body extent -1.7,-0.9 1.7,0.9, height 1.35
1206_180 [mm] "1206_180"
  rect 1.1x1.6 smd: 1(-1.7,0) 2(1.7,0)
  silkscreen extent -0.9,-1 0.9,1, body extent -1.75,-0.95 1.75,0.95, height 1.8
AssemblyNote [mil] "Assembly Note"
AssemblyNoteLabel [mil] "Assembly Note for PCB Labels"
B32774_3150x2200x3650 [mm] "TH, 2-Leads, Body 31.5x22mm, Pin Spacing 27.5mm"
  round 1.55 hole 1.05: 1(-13.75,0) 2(13.75,0)
  silkscreen extent -15.75,-11 15.75,11, body extent -15.75,-11 15.75,11, height 36.5
D0008A_N [mm] "SOIC, 8-Leads, Body 4.9x3.9mm, Pitch 1.27mm, IPC Medium Density"
  oval 1.45x0.6 smd: 1(-2.725,1.905) 2(-2.725,0.635) 3(-2.725,-0.635) 4(-2.725,-1.905) 5(2.725,-1.905) 6(2.725,-0.635) 7(2.725,0.635) 8(2.725,1.905)
  silkscreen extent -3.3,-2.5 0.9,2.5, body extent -3,-2.45 3,2.45, height 1.63
DBV0005A_N [mm] "SOT23, 5-Leads, Body 2.9x1.6mm, Pitch 0.95mm, Lead Span 2.8mm, IPC Medium Density"
  rrect17% 1x0.6 smd: 1(-1.375,0.95) 2(-1.375,0) 3(-1.375,-0.95) 4(1.375,-0.95) 5(1.375,0.95)
  silkscreen extent -1.63,-1.55 0.38,1.55, body extent -1.42,-1.46 1.42,1.46, height 1.09
DBV0006A_N [mm] "SOT23, 6-Leads, Body 2.9x1.6mm, Pitch 0.95mm, Lead Span 2.8mm, IPC Medium Density"
  rrect17% 1x0.6 smd: 1(-1.375,0.95) 2(-1.375,0) 3(-1.375,-0.95) 4(1.375,-0.95) 5(1.375,0) 6(1.375,0.95)
  silkscreen extent -1.68,-1.55 0.5,1.55, body extent -1.42,-1.46 1.42,1.46, height 1.12
DBZ0003A_N [mm] "SOT23, 3-Leads, Body 2.9x1.3mm, Pitch 0.95mm, Lead Span 2.4mm, IPC Medium Density"
  rrect17% 1x0.6 smd: 1(-1.2,0.95) 2(-1.2,-0.95) 3(1.2,0)
  silkscreen extent -1.65,-1.5 0.7,1.5, body extent -1.26,-1.46 1.26,1.46, height 0.98
DCY0003A_N [mm] "SOT223/SC73, 4-Leads, Body 6.5x3.5mm, Pitch 2.3mm, Lead Span 7mm, IPC Medium Density"
  rrect11% 1.75x0.9 smd: 1(-3.125,2.3) 2(-3.125,0) 3(-3.125,-2.3)
  rrect6% 1.75x3.2 smd: 4(3.125,0)
  silkscreen extent -3.02,-3.35 1.4,3.47, body extent -3.51,-3.25 3.51,3.25, height 1.8
DDC0005A_N [mm]
  rrect17% 1x0.6 smd: 1(-1.375,0.95) 2(-1.375,0) 3(-1.375,-0.95) 4(1.375,-0.95) 5(1.375,0.95)
  silkscreen extent -1.75,-1.52 0.88,1.53, body extent -1.41,-1.45 1.41,1.45, height 1.1
DWK0014A [mm] "SOIC-14"
  rrect17% 1.65x0.6 smd: 1(-4.875,4.445) 2(-4.875,3.175) 3(-4.875,1.905) 4(-4.875,0.635) 5(-4.875,-0.635) 6(-4.875,-1.905) 7(-4.875,-3.175) 8(-4.875,-4.445) 9(4.875,-4.445) 10(4.875,-3.175) 11(4.875,-1.905) 14(4.875,1.905) 15(4.875,3.175) 16(4.875,4.445)
  body extent -5.17,-5.15 5.17,5.15, height 2.59
DWV0008A [mm] "SOIC, 8-Leads, Body 5.95x7.6mm (max), Pitch 1.27mm"
  rrect17% 1.8x0.6 smd: 1(-5.45,1.905) 2(-5.45,0.635) 3(-5.45,-0.635) 4(-5.45,-1.905) 5(5.45,-1.905) 6(5.45,-0.635) 7(5.45,0.635) 8(5.45,1.905)
  silkscreen extent -6.25,-2.95 2.98,2.95, body extent -5.77,-2.92 5.77,2.93, height 2.67
ESD_Overlay_Medium [mil]
  silkscreen extent -127,-109 125,110
FCC_disclaimer [mil]
Fiducial10-20 [mm]
  round 1 smd mask+0.5: 1(0,0)
  Top Layer keep-out circle w1.178: c0,0 r0.5
IEC_Caution_Medium [mil]
  silkscreen extent -217,-182 217,193
IEC_HighVoltage_medium [mil]
  silkscreen extent -217,-176 217,200
IEC_HotSurface_Medium [mil]
  silkscreen extent -217,-188 217,188
IXYS_E2 [mm] "Six-Pack Trench IGBT, Body 107.5x45mm"
  round 2.2 hole 1.7: 1(-30.48,20.95) 2(-26.67,20.95) 3(-19.05,20.95) 4(-15.24,20.95) 5(-7.62,20.95) 6(-3.81,20.95) 7(3.81,20.95) 8(7.62,20.95) 9(15.24,20.95) 10(19.05,20.95) 11(26.67,20.95) 12(30.48,20.95) 13(39.6,11.43) 14(39.6,7.62) 15(39.6,-7.62) 16(39.6,-11.43) 17(30.48,-20.95) 18(26.67,-20.95) 19(15.24,-20.95) 20(11.43,-20.95) 21(-3.81,-20.95) 22(-7.62,-20.95) 23(-22.86,-20.95) 24(-26.67,-20.95) 25(-39.6,-11.43) 26(-39.6,-7.62) 27(-39.6,7.62) 28(-39.6,11.43)
  round 2.5 hole 2.5 unplated mask+0.127: MH1(-46.5,16) MH2(-46.5,-16) MH4(46.5,16) MH5(46.5,-16)
  round 6 hole 6 unplated paste+0 mask+0.127: MH3(-46.5,0) MH6(46.5,0)
  silkscreen extent -53.9,-22.6 53.9,23.1, body extent -53.9,-22.6 53.9,22.6, height 17.5
Keystone5000 [mil] "For Keystone 500x miniature loop terminals"
  round 80 hole 40: 1(0,0)
  silkscreen extent -58,-58 58,58, body extent -49,-49 49,49, height 182
Keystone_1902C [mil] "Hex Standoff, 4-40 threaded, nylon"
  round 1 on Mech4: 0(0,0)
  body extent -145,-126 146,126, height 501
Label_650x200 [mil] "Thermal Transfer Label"
  round 1 on Mech13: 0(0,0)
  silkscreen extent -325,-100 325,100, body extent -325,-100 325,100, height 1
MH3.2_H5_W6_KO8_STARHEAD [mil]
  round 20 / inner round 142 / far side round 20 hole 128 unplated mask+65: 1(0,0)
  Keep-Out Layer region: 160.49,0 158.52,25.11 152.64,49.6 143,72.86 129.84,94.34 113.49,113.49 94.34,129.84 72.86,143 49.6,152.64 25.11,158.52 0,160.49 -25.11,158.52 -49.6,152.64 -72.86,143 -94.34,129.84 -113.49,113.49 -129.84,94.34 -143,72.86 -152.64,49.6 -158.52,25.11 -160.49,0 -158.52,-25.11 -152.64,-49.6 -143,-72.86 -129.84,-94.34 -113.49,-113.49 -94.34,-129.84 -72.86,-143 -49.6,-152.64 -25.11,-158.52 0,-160.49 25.11,-158.52 49.6,-152.64 72.86,-143 94.34,-129.84 113.49,-113.49 129.84,-94.34 143,-72.86 152.64,-49.6 158.52,-25.11
  silkscreen extent -120,-120 120,120
MicroSMP [mm] "SMD, 2-Leads, Body 2.2x1.3mm"
  rect 2x1.1 smd: 1(-0.65,0)
  rect 0.8x0.8 smd: 2(1.25,0)
  silkscreen extent -2.2,-1 1.6,1, body extent -1.15,-0.7 1.15,0.7, height 0.75
Mill-Max_800-10-002-10-001000 [mm] "Mill-Max"
  rect 1.5x1.5 hole 0.85: 1(-1.27,0)
  round 1.5 hole 0.85: 2(1.27,0)
  silkscreen extent -2.54,-1.27 2.54,1.78, body extent -2.54,-1.27 2.54,1.27, height 8.13
PAD_100mil-40milhole [mil]
  round 100 hole 40: 1(0,0)
Pb-Free_Overlay_Small [mil]
  silkscreen extent -46,-46 46,46
PWR44412-2SD [mm] "TH, 2-Leads, Pin Spacing 20.32mm"
  round 2.2 hole 1.7: 1(-10.16,0) 2(10.16,0)
  silkscreen extent -10.66,-2.4 10.67,2.4, body extent -10.66,-2.4 10.67,2.4, height 25.4
SMA [mm] "Molded Diode, 2-Leads, Body 4.3x2.6mm, IPC Medium Density, based on OnSemi component dimensions and land pattern"
  rect 2x2 smd: 1(-2,0) 2(2,0)
  silkscreen extent -3.66,-1.57 2.79,1.57, body extent -2.6,-1.3 2.6,1.3, height 2.42
SMB [mil] "Molded Diode, 2-Leads, Body 5.4x3.6mm, IPC Medium Density, based on OnSemi component dimensions"
  rect 85x107.99 smd: 1(-87.01,0) 2(87.01,0)
  silkscreen extent -155,-82 125,82, body extent -106,-71 106,71, height 91
TEC_282834-2 [mm] "TEC"
  rect 1.6x1.6 hole 1.1: 1(-1.27,0)
  round 1.6 hole 1.1: 2(1.27,0)
  silkscreen extent -3.66,-3.4 2.9,3.4, body extent -2.77,-3.25 2.77,3.25, height 10.01
TSW-110-07-G-D [mm] "Samtec 100mil, 2x10, 230 mil above insulator"
  rrect6% 1.65x1.65 hole 1.016: 1(-11.43,-1.27)
  round 1.65 hole 1.016: 2(-11.43,1.27) 3(-8.89,-1.27) 4(-8.89,1.27) 5(-6.35,-1.27) 6(-6.35,1.27) 7(-3.81,-1.27) 8(-3.81,1.27) 9(-1.27,-1.27) 10(-1.27,1.27) 11(1.27,-1.27) 12(1.27,1.27) 13(3.81,-1.27) 14(3.81,1.27) 15(6.35,-1.27) 16(6.35,1.27) 17(8.89,-1.27) 18(8.89,1.27) 19(11.43,-1.27) 20(11.43,1.27)
  silkscreen extent -12.7,-3.24 12.7,2.54, body extent -12.7,-2.54 12.7,2.54, height 8.38
Wurth_7461086 [mm] "Bush, M4, TH"
  round 2 hole 1.475: 1(-3.81,-3.81) 1(-3.81,-1.27) 1(-3.81,1.27) 1(-3.81,3.81) 1(-1.27,-3.81) 1(-1.27,3.81) 1(1.27,-3.81) 1(1.27,3.81) 1(3.81,-3.81) 1(3.81,-1.27) 1(3.81,1.27) 1(3.81,3.81)
  round 0 hole 5.3 unplated mask+0.127: ""(0,0)
  body extent -4.5,-4.5 4.5,4.5, height 6.1

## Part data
C1 C2 C15 C16 C29 C30: library part CMP-0006980-4, "CAP, CERM, 0.1 uF, 16 V, +/- 10%, X7R, 0603", Cap_Case=0603, Manufacturer=Kemet, Supplier Part Number 1=399-5344-1-ND, TempCo=X7R, Tolerance_%=10%, Value1=Unknown, Value2=16V, ValueDisplayed=0.1uF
